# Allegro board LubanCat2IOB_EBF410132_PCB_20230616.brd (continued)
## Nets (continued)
GND: C3.2 C4.2 C5.2 C6.2 C7.2 C8.2 C9.2 C10.2 C12.2 C13.2 C15.2 C16.2 C17.2 C18.2 C19.2 C21.2 C22.2 C23.2 C25.2 C26.2 C27.2 C28.2 C30.2 C31.2 C33.2 C34.2 C35.2 C36.2 C37.2 C38.2 C39.2 C40.2 C41.2 C42.2 C43.2 C44.2 C45.2 C46.2 C47.2 C48.2 C51.2 C52.2 C55.2 C56.2 C57.2 C58.2 C59.2 C63.2 C64.2 C65.2 C66.2 C67.2 C70.2 C71.2 C72.2 C73.2 C74.2 C75.2 C76.2 C77.2 C78.2 C79.2 C80.2 C81.2 C82.2 C83.2 C84.2 C85.2 C86.2 C87.2 C88.2 C89.2 C90.2 C91.2 C92.2 C93.2 C94.2 C95.2 C96.2 C97.2 C98.2 C99.2 C100.2 C101.2 C102.2 C103.2 C104.2 C105.2 C106.2 C107.2 C108.2 C109.2 C110.2 C111.2 C112.2 C113.2 C114.2 C115.2 C116.2 C117.2 C118.2 C119.2 C120.2 C121.2 C122.2 C129.2 C130.2 C131.2 C132.2 C133.2 C134.2 C135.2 C136.2 C137.2 C138.2 C141.2 C144.2 C145.2 C146.2 C147.2 C148.2 C149.2 C150.2 C151.2 C152.2 C153.2 C154.2 C155.2 C156.2 C157.2 C158.2 C159.2 C160.2 C161.2 C162.2 C163.2 C164.2 C165.2 C166.2 C167.2 C168.2 C169.2 C170.2 C171.2 C172.2 C173.2 C174.2 C175.2 C176.2 C179.2 C180.2 C181.2 C182.2 C183.2 C184.2 C185.2 C186.2 C187.2 C188.2 C189.2 C190.2 C191.2 C192.2 C193.2 C194.2 C195.2 C196.2 C197.2 C198.2 C199.2 C200.2 C201.2 C202.2 C203.2 C204.2 C207.2 C208.2 C209.2 C210.2 C212.2 C213.2 C216.2 C218.2 D1.1 D2.1 D3.1 D6.2 D7.2 D8.2 D9.2 D10.2 D11.2 D12.2 D13.2 D15.1 D16.1 D17.1 D18.1 D19.2 D20.2(A) D23.2 D24.1 D25.2 D26.2 D28.1 D29.2 D30.2 D31.2 D32.2 D33.2 D34.2 D36.2 D37.2 J1.7 J1.8 J1.9 J1.10 J1.16 J1.20 J1.23 J1.26 J1.31 J1.32 J1.40 J1.49 J1.50 J1.56 J1.66 J1.67 J1.73 J1.76 J2.1 J2.2 J2.8 J2.11 J2.14 J2.27 J2.30 J2.40 J2.41 J2.55 J2.58 J2.64 J2.68 J2.69 J2.75 J2.79 J3.1 J3.2 J3.3 J3.13 J3.18 J3.23 J3.24 J3.26 J3.29 J3.36 J3.39 J3.49 J3.54 J3.55 J3.65 J3.66 J3.79 J3.80 J4.1 J4.2 J4.12 J4.23 J4.26 J4.33 J4.40 J4.54 J4.58 J4.64 J4.69 J4.70 J4.71 J4.73 J4.75 J4.76 J4.77 J4.78 J4.79 J4.80 J6.2 J7.3 J8.2 J8.5 J9.4 J11.10(CHS) J12.4 J15.6 J16.2 J17.1(CONFIG_3) J17.3(GND1) J17.9(GND2) J17.15(GND3) J17.21(CONFIG_0) J17.27(GND4) J17.33(GND5) J17.39(GND_6) J17.45(GND_7) J17.51(GND_8) J17.57(GND_9) J17.71(GND_10) J17.73(GND_11) J17.75(CONFIG_2) J17.76(G1) J17.77(G2) J18.10(CHS) J19.4(GND1) J19.7(GND2) J19.13(GND1) J19.16(NC3) J20.4(GND) J20.10(GND) J21.2 J21.5 J21.8 J21.11 J21.17 J22.4 J22.18 J22.21 J22.23 J22.24 J22.25(SH1) J22.26(SH2) J23.6 J23.7 J23.8 J23.16 J23.19 J23.22 J23.25 J23.28 J23.31(SH1) J23.32(SH2) J24.4 J24.23 J24.24 J24.25(SH1) J24.26(SH2) J26.6 J26.7 J26.8 J26.16 J26.19 J26.22 J26.25 J26.28 J26.31(SH1) J26.32(SH2) J28.6 J29.2 J29.5 J29.8 J29.11 J29.15 J29.16 J29.18 J29.19 J29.20 J29.21 J29.31(SH1) J29.32(SH2) J33.1 J34.1(GND1) J34.4(GND2) J34.7(GND3) J34.S1(SH1) J34.S2(SH2) J35.4(GND9) J35.9(GND1) J35.15(GND2) J35.18(GND10) J35.21(GND3) J35.26(GND11) J35.27(GND4) J35.29(GND5) J35.34(GND12) J35.35(GND6) J35.37(GND7) J35.40(GND13) J35.43(GND8) J35.50(GND14) J35.53 J35.54 J36.A1(GND1) J36.A12(GND2) J36.B1(GND4) J36.B12(GND3) J37.2 J37.4 J37.6 J39.2 J39.3 J40.2 J40.3 J41.6(VSS) J41.10(GND10) J41.11(GND11) J41.12(GND12) J41.13(GND13) L2.2 L19.2 L20.2 L21.2 LED1.2(CATHODE) Q4.2(EMITTER) Q14.2(SOURCE) R3.2 R7.2 R8.2 R12.2 R13.2 R15.2 R17.2 R27.2 R40.2 R41.2 R69.2 R70.2 R74.2 R75.2 R79.2 R82.2 R97.2 R98.2 R99.2 R100.2 R106.2 R108.2 R112.2 R121.2 R125.2 R126.2 R127.2 R131.2 R135.2 R137.2 R142.2 R143.2 R144.2 R155.2 R157.2 R159.2 R162.2 R163.2 R171.2 R173.2 R175.2 R176.2 R177.2 R183.2 R186.2 R188.1 R190.2 R192.2 R196.2 R197.2 R198.2 R199.2 R202.2 R203.2 R207.2 R212.2 R215.2 R216.2 R220.2 R234.2 R237.2 SS5.1(NC_1) SS6.1(NC_1) SS7.1(NC_1) SS8.1(NC_1) SS9.1(NC_1) SS10.1(NC_1) SS11.1(NC_1) SS12.1(NC_1) SS13.1(NC_1) SW1.1(A1) SW1.3(GND1) SW2.1(A1) SW2.3(GND1) SW3.1(A1) SW3.3(GND1) U1.1(GND) U2.1(GND) U3.1(GND1) U3.4(GND2) U4.1(\\O\E) U4.3(GND) U5.1(GND) U6.4(GND) U7.1(GND) U8.5(GND) U9.2(GND) U9.8(S) U10.2(GND) U10.8(S) U11.15(GND) U12.1(\\O\E) U12.3(GND) U13.5(GND) U14.5(GND) U14.8(SH1) U14.9(SH2) U14.10(SH3) U14.11(SH4) U15.2 U16.1(GND) U17.4(GND) U18.41(GND) U19.41(GND) U20.1(GND) U21.9(GNDXD) U21.16(GNDODA) U22.3(GND1) U22.8(GND2) U23.3(GND1) U23.8(GND2) U24.2(GND) U25.2(GND) U26.2(GND) U28.25(VSS) U29.2(GND) U30.3(GND1) U30.8(GND2) U31.3(GND1) U31.8(GND2) U32.3(GND1) U32.8(GND2) U33.2(GND) U34.2(GND) U35.2(GND) U36.2(GND) U37.2(GND) U38.2(GND) U39.2(GND) U40.2(GND) U41.1(GND) Y1.2(GND1) Y1.4(GND2) Y2.2(GND1) Y2.4(GND2) Y3.2(GND1) Y3.4(GND2) Y4.2(GND1) Y4.4(GND2)
VCC3V3_SD: C28.1 C30.1 J1.15 J1.17 J41.4(VDD)
VCC5V0_SYS: C24.2 C25.1 C26.1 J1.1 J1.2 J1.3 J1.4 J1.5 J1.6 L3.2 R4.1 R11.2
VCC5V0_USB: C140.2 C141.1 C159.1 L17.2 R235.2 U24.5(IN) U25.5(IN) U26.5(IN) U29.5(IN)
VCC5V0_USB20_HOST2: C144.1 C145.1 J19.10(VBUS) U24.1(OUT)
VCC5V0_USB20_HUB: C154.1 C155.1 C161.1 C162.1 C164.1 C165.1 J20.1(VBUS) J20.7(VBUS) U28.19(VDD5) U29.1(OUT)
VCC5V0_USB30_HOST: C148.1 C149.1 J19.1(VBUS) U26.1(OUT)
VCC_1V8: C22.1 C23.1 J1.11 J1.13 L10.2 L14.2 Q1.1(GATE) Q2.1(GATE) R24.1 R25.1 R45.1 R46.1 U6.8(VCC)
VCCA_1V8: J1.12 J1.14 R219.1
VCCIO_ACODEC: J1.19 J1.21 R210.1 R213.1
VDD_3V3: C12.1 C13.1 C14.2 C17.1 C21.1 C37.1 C40.1 D21.2 J37.5 L5.1 L6.1 L7.2 L11.2 L12.2 L15.2 L16.2 L35.2 Q6.1(GATE) Q8.1(GATE) R2.2 R6.2 R31.1 R32.1 R33.1 R35.1 R47.1 R48.1 R66.2 R72.1 R146.1 R147.1 R178.1 R180.1 R181.1 R236.2 U4.5(VCC) U9.5(VIO) U10.5(VIO) U12.5(VCC) U35.5(IN) U37.5(IN) U38.5(IN) U40.5(IN)
VDD_3V3_EDP_LCD: C183.1 C184.1 J29.12 J29.13 R187.1 U37.1(OUT)
VDD_3V3_EDP_TP: C202.1 C203.1 J28.1 R193.1 R194.1 U38.1(OUT)
VDD_5V: C2.2 C3.1 C4.1 C36.1 C38.1 C41.1 C43.1 C46.1 C79.1 C80.1 D14.1 J37.3 L1.2 Q3.2(SOURCE) Q7.1(GATE) R1.2 R9.1 U7.3(VIN) U9.3(VCC) U10.3(VCC) U20.3(VIN) U33.5(IN) U34.5(IN) U36.5(IN) U39.5(IN)
VDD_CAM0_5V: C169.1 C170.1 C171.1 J22.1 J22.2 J22.3 U33.1(OUT)
VDD_CAM1_5V: C173.1 C174.1 C175.1 J24.1 J24.2 J24.3 U36.1(OUT)
VDD_LCD0_3V3: C185.1 C190.1 C191.1 J23.4 J23.5 R167.1 R222.1 U35.1(OUT)
VDD_LCD0_5V: C186.1 C187.1 C188.1 J23.1 J23.2 J23.3 U34.1(OUT)
VDD_LCD1_3V3: C196.1 C198.1 C199.1 J26.4 J26.5 R223.1 R224.1 U40.1(OUT)
VDD_LCD1_5V: C194.1 C195.1 C197.1 J26.1 J26.2 J26.3 U39.1(OUT)
BAT_RTC: C67.1 D21.1 D24.2 J16.1
CAM0_NRST: J2.76 J22.22
CAM0_PWDN: J1.39 J22.15
CAM0_PWR_EN: J3.56 R174.1
CAM1_NRST: J2.80 J24.22
CAM1_PWDN: J2.78 J24.15
CAM1_PWR_EN: J3.58 R185.1
CAN1_H: J5.1 R39.1 U9.7(CANH)
CAN1_L: J5.2 R39.2 U9.6(CANL)
CAN1_RX_M1: J4.9 U9.4(RXD)
CAN1_TX_M1: J4.7 U9.1(TXD)
CAN2_H: J5.3 R42.1 U10.7(CANH)
CAN2_L: J5.4 R42.2 U10.6(CANL)
CAN2_RX: Q2.3(DRAIN) R48.2 U10.4(RXD)
CAN2_RX_M0: J4.8 Q2.2(SOURCE) R46.2
CAN2_TX: Q1.3(DRAIN) R47.2 U10.1(TXD)
CAN2_TX_M0: J4.10 Q1.2(SOURCE) R45.2
CC1: D27.2 J36.A5(CC1)
CC2: D27.1 J36.B5(CC2)
CTP0_INT: J3.8 J23.11 R167.2
CTP0_RST: J3.6 J23.12 R222.2
CTP1_INT: J4.49 J26.11 R223.2
CTP1_RST: J4.53 J26.12 R224.2
DGB_RX: D36.1 J7.2 R36.1
DGB_TX: D37.1 J7.1 R23.1
DSI0_RST: J3.16 J23.15
DSI0_TE: J3.4 R204.1
DSI1_RST: J4.57 J26.15
DSI1_TE: J4.55 R208.1
EDP_AUXN: C178.2 J29.10 R188.2
EDP_AUXP: C177.2 J29.9 R187.2
EDP_BL_EN: J4.45 J29.22
EDP_BL_PWM: J3.14 J29.23
EDP_HPDIN_M0: J2.66 J29.17
EDP_LCD_PWR_EN: J3.60 R189.2
EDP_TP_INT: J4.51 J28.2 R193.2
EDP_TP_PWR_EN: J3.64 R191.1
EDP_TP_RESET: J4.47 J28.3 R194.2
EDP_TX_AUXN: C178.1 J2.62
EDP_TX_AUXP: C177.1 J2.60
EDP_TX_D0N: J2.44 J29.6
EDP_TX_D0P: J2.42 J29.7
EDP_TX_D1N: J2.48 J29.3
EDP_TX_D1P: J2.46 J29.4
EXT_PWR_EN: J1.27 R8.1 U2.5(EN)
FAN_CTRL: J3.5 R10.1
FSPI_CLK: J2.29 U6.6(CLK)
FSPI_CS0N: J2.31 U6.1(C\S\)
FSPI_D0: J2.33 J32.1 U6.5(DI/IO0)
FSPI_D1: J2.35 U6.2(DO/IO1)
FSPI_D2: J2.37 R24.2 U6.3(W\P\/IO2)
FSPI_D3: J2.39 R25.2 U6.7(HOLD/IO3)
GMAC0_INT: J2.70 R104.1
GMAC0_MCLKINOUT: J2.77 R105.1 R106.1
GMAC0_MDC: J2.73 R101.2 U18.13(MDC)
GMAC0_MDIO: J2.71 R102.2 U18.14(MDIO)
GMAC0_RSTN: D22.2 J2.72
GMAC0_RXCLK: J2.57 R95.1 R98.1
GMAC0_RXD0: J2.67 R88.2 R91.1
GMAC0_RXD1: J2.65 R89.2 R92.1
GMAC0_RXD2: J2.63 R93.1 R97.1
GMAC0_RXD3: J2.61 R90.2 R94.1
GMAC0_RXDV_CRS: J2.59 R96.1 R99.1
GMAC0_TXCLK: J2.51 U18.20(TXC)
GMAC0_TXD0: J2.49 U18.18(TXD0)
GMAC0_TXD1: J2.47 U18.17(TXD1)
GMAC0_TXD2: J2.45 U18.16(TXD2)
GMAC0_TXD3: J2.43 U18.15(TXD3)
GMAC0_TXEN: J2.53 U18.19(TXCTL)
GMAC1_INT: J3.12 R132.1
GMAC1_MCLKINOUT_M1: J4.56 R134.1 R135.1
GMAC1_MDC_M1: J4.62 R128.2 U19.13(MDC)
GMAC1_MDIO_M1: J4.60 R129.2 U19.14(MDIO)
GMAC1_RSTN: D35.2 J3.10
GMAC1_RXCLK_M1: J4.36 R117.2 R123.1
GMAC1_RXD0_M1: J4.34 R115.2 R118.1
GMAC1_RXD1_M1: J4.32 R116.2 R119.1
GMAC1_RXD2_M1: J4.30 R120.1 R125.1
GMAC1_RXD3_M1: J4.28 R122.1 R126.1
GMAC1_RXDV_CRS_M1: J4.38 R124.1 R127.1
GMAC1_TXCLK_M1: J4.44 U19.20(TXC)
GMAC1_TXD0_M1: J4.52 U19.18(TXD0)
GMAC1_TXD1_M1: J4.50 U19.17(TXD1)
GMAC1_TXD2_M1: J4.48 U19.16(TXD2)
GMAC1_TXD3_M1: J4.46 U19.15(TXD3)
GMAC1_TXEN_M1: J4.42 U19.19(TXCTL)
HDMI_5V: C168.1 D14.2 D28.2 J21.18 R179.1 R182.1
HDMI_GND_CHASSIS: J21.G1(20) J21.G2(21) J21.G3(22) J21.G4(23) R177.1
HDMI_TX0N_PORT: J3.48 J21.9 U32.1(D1+) U32.10(NC1)
HDMI_TX0P_PORT: J3.46 J21.7 U32.2(D1-) U32.9(NC2)
HDMI_TX1N_PORT: J3.44 J21.6 U31.2(D1-) U31.9(NC2)
HDMI_TX1P_PORT: J3.42 J21.4 U31.1(D1+) U31.10(NC1)
HDMI_TX2N_PORT: J3.40 J21.3 U32.4(D2+) U32.7(NC3)
HDMI_TX2P_PORT: J3.38 J21.1 U32.5(D2-) U32.6(NC4)
HDMI_TX_CEC_PORT: D18.2 J21.13 Q7.3(DRAIN)
HDMI_TX_HPD_PORT: D15.2 J21.19 R172.2 R176.1
HDMI_TX_HPDIN: J3.34 R172.1
HDMI_TXCLKN_PORT: J3.50 J21.12 U31.5(D2-) U31.6(NC4)
HDMI_TXCLKP_PORT: J3.52 J21.10 U31.4(D2+) U31.7(NC3)
HDMI_TXDDC_SCL_PORT: D17.2 J21.15 Q6.3(DRAIN) R179.2
HDMI_TXDDC_SDA_PORT: D16.2 J21.16 Q8.3(DRAIN) R182.2
HDMITX_CEC_M0: J3.32 Q7.2(SOURCE) R180.2
HDMITX_SCL: J3.30 Q6.2(SOURCE) R178.2
HDMITX_SDA: J3.28 Q8.2(SOURCE) R181.2
HP_DET: C213.1 J1.35 R211.1
HP_SNS: J1.36 J25.5 J27.5 R212.1 R216.1
HPL_OUT: C214.1 J1.34
HPR_OUT: C215.1 J1.38
HUB_3V3: C156.1 C157.1 R164.2 R165.2 R166.2 R168.2 R169.1 U28.20(VDD33F)
I2C0_SCL: J2.3 U17.6(SCL)
I2C0_SDA: J2.5 U17.5(SDA)
I2C1_SCL: J2.7 J22.6 J23.9 R35.2
I2C1_SDA: J2.9 J22.5 J23.10 R33.2
I2C5_SCL_M0: J4.25 J24.6 J26.9 J28.4 R147.2
I2C5_SDA_M0: J4.27 J24.5 J26.10 J28.5 R146.2
LCD0_BL_PWM: J3.9 J23.13
LCD0_PWR_EN: J4.65 R195.1
LCD1_BL_PWM: J3.11 J26.13
LCD1_PWR_EN: J4.67 R200.2
LED_USR: J4.4 LED2.2(CATHODE)
M2PCIE_3V3: C69.2 C70.1 C71.1 C115.1 C116.1 C117.1 C118.1 C119.1 C120.1 C121.1 C122.1 C129.1 C130.1 C131.1 C136.1 J17.2(3.3V_1) J17.4(3.3V_2) J17.12(3.3V_3) J17.14(3.3V_4) J17.16(3.3V_5) J17.18(3.3V_6) J17.70(3.3V_7) J17.72(3.3V_8) J17.74(3.3V_9) L8.2 R73.2 R80.2 R81.2 R83.1 R84.1 R85.1 R86.1 R145.2 U21.1(VDDXD)
M2PCIE_PWR_EN: J1.41 R76.2
MDIN0_PHY0: J11.3(TD1-) U18.2(MDIN0)
MDIN0_PHY1: J18.3(TD1-) U19.2(MDIN0)
MDIN1_PHY0: J11.7(RD1-) U18.5(MDIN1)
MDIN1_PHY1: J18.7(RD1-) U19.5(MDIN1)
MDIN2_PHY0: J11.6(TD2-) U18.7(MDIN2)
MDIN2_PHY1: J18.6(TD2-) U19.7(MDIN2)
MDIN3_PHY0: J11.9(RD2-) U18.10(MDIN3)
MDIN3_PHY1: J18.9(RD2-) U19.10(MDIN3)
MDIP0_PHY0: J11.2(TD1+) U18.1(MDIP0)
MDIP0_PHY1: J18.2(TD1+) U19.1(MDIP0)
MDIP1_PHY0: J11.4(RD1+) U18.4(MDIP1)
MDIP1_PHY1: J18.4(RD1+) U19.4(MDIP1)
MDIP2_PHY0: J11.5(TD2+) U18.6(MDIP2)
MDIP2_PHY1: J18.5(TD2+) U19.6(MDIP2)
MDIP3_PHY0: J11.8(RD2+) U18.9(MDIP3)
MDIP3_PHY1: J18.8(RD2+) U19.9(MDIP3)
MIC1_INN: C217.2 D30.1 J1.30 J27.3 J27.4 J30.1 R215.1
MIC1_INP: C217.1 D29.1 J1.28 J27.1 J27.2 J30.2 R214.2
MINIPCIE_3V3: C32.1 C33.1 C34.1 C35.1 C55.1 C56.1 C57.1 C58.1 J35.2(VBAT1) J35.24(VBAT5) J35.39(VBAT2) J35.41(VBAT3) J35.52(VBAT4) L4.2 R14.1 R22.1
MINIPCIE_NWDISABLE: J4.61 R62.2
MINIPCIE_PWR_EN: J4.63 R16.1
MIPI_CSI_RX_CLK0N: J3.78 J22.10
MIPI_CSI_RX_CLK0P: J3.76 J22.9
MIPI_CSI_RX_CLK1N: J3.77 J24.10
MIPI_CSI_RX_CLK1P: J3.75 J24.9
MIPI_CSI_RX_D0N: J3.70 J22.12
MIPI_CSI_RX_D0P: J3.68 J22.11
MIPI_CSI_RX_D1N: J3.74 J22.8
MIPI_CSI_RX_D1P: J3.72 J22.7
MIPI_CSI_RX_D2N: J3.69 R227.1 R233.1
MIPI_CSI_RX_D2P: J3.67 R226.1 R232.1
MIPI_CSI_RX_D3N: J3.73 R229.1 R231.1
MIPI_CSI_RX_D3P: J3.71 R228.1 R230.1
MIPI_DSI_TX0_CLKN: J3.53 J23.24
MIPI_DSI_TX0_CLKP: J3.51 J23.23
MIPI_DSI_TX0_D0N: J3.43 J23.27
MIPI_DSI_TX0_D0P: J3.41 J23.26
MIPI_DSI_TX0_D1N: J3.47 J23.21
MIPI_DSI_TX0_D1P: J3.45 J23.20
MIPI_DSI_TX0_D2N: J3.59 J23.18
MIPI_DSI_TX0_D2P: J3.57 J23.17
MIPI_DSI_TX0_D3N: J3.63 J23.30
MIPI_DSI_TX0_D3P: J3.61 J23.29
MIPI_DSI_TX1_CLKN: J3.27 J26.24
MIPI_DSI_TX1_CLKP: J3.25 J26.23
MIPI_DSI_TX1_D0N: J3.17 J26.27
MIPI_DSI_TX1_D0P: J3.15 J26.26
MIPI_DSI_TX1_D1N: J3.21 J26.21
MIPI_DSI_TX1_D1P: J3.19 J26.20
MIPI_DSI_TX1_D2N: J3.33 J26.18
MIPI_DSI_TX1_D2P: J3.31 J26.17
MIPI_DSI_TX1_D3N: J3.37 J26.30
MIPI_DSI_TX1_D3P: J3.35 J26.29
OE: R83.2 U21.8(OE)
ON/OFF_KEY: C64.1 D2.2 J1.25 SW2.2(B1)
PCIE20_CLKREQN_M1: J4.37 R30.1
PCIE20_PERSTN_M1: J4.59 R63.2
PCIE20_REFCLKN: J1.54 J35.11(VDD-EXT)
PCIE20_REFCLKP: J1.52 J35.13(RESERVED)
PCIE20_RXN: J1.48 J35.23(UART-RXD)
PCIE20_RXP: J1.46 J35.25(UART-RTS)
PCIE20_TXN: C53.1 J1.44
PCIE20_TXP: C54.1 J1.42
PCIE20_WAKEN_M1: J4.39 R29.1
PCIE30_REFCLKN_IN: J1.71 R78.2 R79.1
PCIE30_REFCLKP_IN: J1.69 R77.2 R82.1
PCIE30_RX0N: J1.61 J17.41(SATA-/B+/PERN0)
PCIE30_RX0P: J1.59 J17.43(SATA-/B-/PERP0)
PCIE30_RX1N: J1.65 J17.29(PERN1)
PCIE30_RX1P: J1.63 J17.31(PERP1)
PCIE30_TX0N: C125.1 J1.53
PCIE30_TX0P: C126.1 J1.51
PCIE30_TX1N: C123.1 J1.57
PCIE30_TX1P: C124.1 J1.55
PCIE30X2_CLKREQN_M1: J1.75 J17.52(CLKREQ#)
PCIE30X2_PERSTN_M1: J1.79 J17.50(PERST#)
PCIE30X2_WAKEN_M1: J1.77 J17.54(PEWAKE#)
PDN: R84.2 U21.7(PDN)
PE_TXN: C53.2 J35.31(UART-TXD)
PE_TXP: C54.2 J35.33(PERST2)
PETN0: C125.2 J17.47(SATA-/A-/PETN0)
PETN1: C123.2 J17.35(PETN1)
PETP0: C126.2 J17.49(SATA-/A+/PETP0)
PETP1: C124.2 J17.37(PETP1)
PHY0_CLKOUT125: R105.2 U18.35(CLKOUT)
PHY0_LED1: J11.14(YELA) R108.1 U18.33(LED1)
PHY0_LED2: J11.12(GRLC) R109.1 U18.34(LED2)
PHY1_CLKOUT125: R134.2 U19.35(CLKOUT)
PHY1_LED1: J18.14(YELA) R137.1 U19.33(LED1)
PHY1_LED2: J18.12(GRLC) R138.1 U19.34(LED2)
PWM3_IR: J3.7 R34.1
RECOVERY_KEY: J2.16 R26.2
REF_CLKN: C127.1 R111.2 R112.1
REF_CLKP: C128.1 R87.2 R142.1
REFCLKN: C127.2 J17.53(REFCLKN)
REFCLKP: C128.2 J17.55(REFCLKP)
RESET_KEY: C63.1 D1.2 J1.29 SW1.2(B1)
RS232_3V3: C42.1 L7.1 U11.16(VCC)
RS232_R1IN: J8.4 U11.13(R1IN)
RS232_R1OUT: J13.1 U11.12(R1OUT)
RS232_R2IN: J8.1 U11.8(R2IN)
RS232_R2OUT: J14.1 U11.9(R2OUT)
RS232_T1IN: J13.2 U11.11(T1IN)
RS232_T1OUT: J8.6 U11.14(T1OUT)
RS232_T2IN: J14.2 U11.10(T2IN)
RS232_T2OUT: J8.3 U11.7(T2OUT)
RS485_1_3V3: C39.1 D4.1 L5.2 U8.8(VCC)
RS485_1_A: J10.2 R37.1 R38.2 U8.6(A)
RS485_1_B: J10.1 R38.1 R41.1 U8.7(B)
RS485_1_DIR: J4.41 R40.1 U8.2(R\E\) U8.3(DE)
RS485_2_3V3: C44.1 D5.1 L6.2 U13.8(VCC)
RS485_2_A: J10.4 R67.1 R68.2 U13.6(A)
RS485_2_B: J10.3 R68.1 R70.1 U13.7(B)
RS485_2_DIR: J4.43 R69.1 U13.2(R\E\) U13.3(DE)
RX8010_NIRQ1: J1.33 R72.2 U17.7(/IRQ1)
S0: R86.2 U21.2(S0)
S1: R85.2 U21.3(S1)
S2: R143.1 U21.4(S2)
SARADC_VIN1: J2.18 R55.1
SARADC_VIN3: J2.20 R219.2 R220.1
SARADC_VIN4: J2.22 R56.1
SARADC_VIN5: J2.24 R58.1
SARADC_VIN6: J2.26 R59.1
SARADC_VIN7: J2.28 R71.1
SATA0_RXN: C62.1 J1.70
SATA0_RXP: C211.1 J1.68
SATA0_TXN: C61.1 J1.74
SATA0_TXP: C60.1 J1.72
SATA0RXN: C62.2 J34.5(RXDN)
SATA0RXP: C211.2 J34.6(RXDP)
SATA0TXN: C61.2 J34.3(TXDN)
SATA0TXP: C60.2 J34.2(TXDP)
SATA_5V: C206.2 C207.1 C208.1 J40.1 L22.2 R201.2
SATA_12V: C59.1 C212.1 J40.4 Q10.3(DRAIN)
SATA_PWR_EN: J2.74 R206.1 R209.2
SDMMC0_CLK: J2.13 R54.1
SDMMC0_CMD: J2.15 R53.1
SDMMC0_D0: J2.19 R57.1
SDMMC0_D1: J2.21 R60.1
SDMMC0_D2: J2.23 R51.1
SDMMC0_D3: J2.25 R52.1
SDMMC0_DET: J2.17 R61.1
SIM_CLK0: J35.12(USIM-CLK) R20.1
SIM_DATA0: J35.10(USIM-DATA) R21.1
SIM_RST0: J35.14(USIM-RST) R19.1
SIM_VDD: J35.8(USIM-VDD) R18.1 U14.1(VCC) U15.6
SPKN_OUT: J1.24 R218.1
SPKP_OUT: J1.22 R217.1
U7_RX: J9.3 J13.5
U7_TX: J9.2 J13.6
U9_RX: J12.3 J14.5
U9_TX: J12.2 J14.6
UART2_RX: R36.2 U12.2(A)
UART2_RX_M0_DEBUG: J3.22 U12.4(Y)
UART2_TX: R23.2 U4.4(Y)
UART2_TX_M0_DEBUG: J3.20 U4.2(A)
UART3_RX_M1: J4.13 U8.1(RXD)
UART3_TX_M1: J4.11 U8.4(TXD)
UART4_RX_M1: J4.17 U13.1(RXD)
UART4_TX_M1: J4.15 U13.4(TXD)
UART7_RX: D9.1 J13.3 R50.2
UART7_RX_M1: J4.21 R50.1
UART7_TX: D8.1 J13.4 R49.2
UART7_TX_M1: J4.19 R49.1
UART9_RX: D7.1 J14.3 R44.2
UART9_RX_M1: J4.5 R44.1
UART9_TX: D6.1 J14.4 R43.2
UART9_TX_M1: J4.3 R43.1
USB2_HOST2_DM: J4.74 R152.2
USB2_HOST2_DP: J4.72 R153.2
USB2_HOST3_DM: J4.68 U28.14(DMU)
USB2_HOST3_DP: J4.66 U28.15(DPU)
USB3_HOST1_DM: J1.80 R148.2
USB3_HOST1_DP: J1.78 R149.2
USB3_HOST1_SSRXN: J1.60 R150.2
USB3_HOST1_SSRXP: J1.58 R151.2
USB3_HOST1_SSTXN: C142.2 J1.64
USB3_HOST1_SSTXP: C143.2 J1.62
USB3_OTG0_DM: D26.1 J2.6 J36.A7(DN1) J36.B7(DN2)
USB3_OTG0_DP: D25.1 J2.4 J36.A6(DP1) J36.B6(DP2)
USB3_OTG0_ID: J2.10 R160.2
USB3_OTG0_VBUSDET: J2.12 R158.2 R159.1
USB20_DM1: J19.11(D-) R152.1 U22.4(D2+) U22.7(NC3)
USB20_DP1: J19.12(D+) R153.1 U22.5(D2-) U22.6(NC4)
USB20_HOST2_PWR_EN: J1.45 R154.1
USB20_HUB_PWR_EN: J3.62 R170.1
USB30_DM: J19.2(D-) R148.1 U23.5(D2-) U23.6(NC4)
USB30_DP: J19.3(D+) R149.1 U23.4(D2+) U23.7(NC3)
USB30_HOST1_PWR_EN: J1.47 R156.1
USB30_RXN: J19.5(RX-) R150.1 U23.2(D1-) U23.9(NC2)
USB30_RXP: J19.6(RX+) R151.1 U23.1(D1+) U23.10(NC1)
USB30_TXN: C142.1 J19.8(TX-) U22.2(D1-) U22.9(NC2)
USB30_TXP: C143.1 J19.9(TX+) U22.1(D1+) U22.10(NC1)
USB_HUB_DM1: J20.2(D-) U28.11(DM1) U30.2(D1-) U30.9(NC2)
USB_HUB_DM2: J20.8(D-) U28.9(DM2) U30.5(D2-) U30.6(NC4)
USB_HUB_DM3: R64.2 U28.7(DM3)
USB_HUB_DP1: J20.3(D+) U28.12(DP1) U30.1(D1+) U30.10(NC1)
USB_HUB_DP2: J20.9(D+) U28.10(DP2) U30.4(D2+) U30.7(NC3)
USB_HUB_DP3: R65.2 U28.8(DP3)
USB_OTG_VBUS: C151.1 C152.1 D23.1 J36.A4(VBUS1) J36.A9(VBUS2) J36.B4(VBUS4) J36.B9(VBUS3) R158.1 U25.1(OUT)
USB_OTG_VBUS_EN: J1.43 R161.1
N28501: C20.1 U5.6(BOOT)
N28533: C20.2 L3.1 U5.2(SW)
N28611: C24.1 R11.1 R13.1 U5.4(FB)
N15580021: R91.2 U18.25(RXD0)
N15580025: R92.2 U18.24(RXD1)
N15580029: R93.2 U18.23(RXD2)
N15580033: R94.2 U18.22(RXD3)
N15580037: R95.2 U18.27(RXC)
N15580041: R96.2 U18.26(RXCTL)
N15582684: R103.2 R104.2 U18.31(INTB)
N15584123: C77.1 U18.36(XTAL_IN) Y3.3
N15584130: C76.1 U18.37(XTAL_OUT) Y3.1
N15584385: C78.1 D22.1 R107.2 R184.2 U18.12(PHYRSTB)
N15584944: R110.1 U18.32(LED0)
N15590150: L9.1 U18.30(REG_OUT)
N15590489: R100.1 U18.39(RSET)
N15599533: R118.2 U19.25(RXD0)
N15599537: R119.2 U19.24(RXD1)
N15599541: R120.2 U19.23(RXD2)
N15599545: R122.2 U19.22(RXD3)
N15599549: R123.2 U19.27(RXC)
N15599553: R124.2 U19.26(RXCTL)
N15600826: R130.2 R132.2 U19.31(INTB)
N15601838: C98.1 U19.37(XTAL_OUT) Y4.1
N15601846: C99.1 U19.36(XTAL_IN) Y4.3
N15602147: C101.1 D35.1 R136.2 R238.2 U19.12(PHYRSTB)
N15602572: R139.1 U19.32(LED0)
N15603170: C100.1 J18.1(CT)
N15605093: L13.1 U19.30(REG_OUT)
N15605512: R121.1 U19.39(RSET)
N15772454: J26.14 R208.2
N15774097: J23.14 R204.2
N16795890: R12.1 R225.1 U5.5(EN)
N17344359: J39.1 J39.5 L2.1
N17345181: C11.2 L35.1 U2.2(SW)
N17345183: C14.1 R6.1 R7.1 U2.4(FB)
N17345235: C11.1 U2.6(BOOT)
N17366990: C1.1 U1.6(BOOT)
N17366996: C1.2 L1.1 U1.2(SW)
N17367006: C2.1 R1.1 R3.1 U1.4(FB)
N17371141: LED1.1(ANODE) R4.2
N17385739: LED2.1(ANODE) R31.2
N17407470: J41.1(DAT2) R51.2
N17407472: J41.7(DAT0) R57.2
N17407474: J41.5(CLK) R54.2
N17407476: J41.3(CMD) R53.2
N17407478: J41.2(CD/DAT3) R52.2
N17407480: J41.8(DAT1) R60.2
N17407510: J41.9(CD) R61.2
N17408573: C31.1 J11.1(CT)
N17409816: C29.1 L4.1 U7.2(SW)
N17409833: R16.2 R17.1 U7.5(EN)
N17409879: C32.2 R14.2 R15.1 U7.4(FB)
N17410026: C29.2 U7.6(BOOT)
N17410340: C52.1 R19.2 U14.2(RST) U15.5
N17410342: C51.1 R20.2 U14.3(CLK) U15.4
N17410344: C47.1 R18.2 R21.2 U14.7(I/O) U15.1
N17411312: J35.1(MIC-P) R22.2 R29.2
N17411326: J35.7(SPK-N) R30.2
N17411361: J35.20(W-DISABLE) R62.1
N17411393: J35.22(PERST1) R63.1
N17411481: J35.38(USB-D+) R65.1
N17411507: J35.36(USB-D-) R64.1
N17438974: D4.2 R37.2
N17440531: D5.2 R67.2
N17441588: C49.1 U11.3(C1-)
N17441590: C49.2 U11.1(C1+)
N17441592: C50.1 U11.5(C2-)
N17441594: C50.2 U11.4(C2+)
N17441596: C48.1 U11.6(V-)
N17441598: C45.1 U11.2(V+)
N17468430: C66.1 D21.3 U17.8(VDD)
N17485809: R75.1 R76.1 U20.5(EN)
N17485853: C68.1 U20.6(BOOT)
N17485857: C68.2 L8.1 U20.2(SW)
N17485876: C69.1 R73.1 R74.1 U20.4(FB)
N17487342: J17.38(DEVSLP) R81.1
N17487441: J17.10(DAS/DSS) R80.1
N17494240: J19.19(SH1) J19.20(SH2) J19.21(SH1) J19.22(SH2) L19.1
N17495021: C147.1 R156.2 U26.4(EN)
N17495041: R157.1 U26.3(ISET)
N17495139: C146.1 R154.2 U24.4(EN)
N17495165: R155.1 U24.3(ISET)
N17495663: J36.C1(SH1) J36.C2(SH2) J36.C3(SH3) J36.C4(SH4) L20.1
N17495859: D27.3 R160.1
N17496265: R162.1 U25.3(ISET)
N17496334: C150.1 R161.2 U25.4(EN)
N17505436: R163.1 U28.13(REXT)
N17505526: R164.1 U28.16(XRSTJ)
N17505593: R165.1 U28.18(BUSJ)
N17505596: C153.1 R166.1 U28.17(VBUSM)
N17506485: R168.1 U28.21(DRV)
N17506866: C158.1 R169.2 U28.1(OVCJ)
N17515649: C138.1 U28.3(XOUT) Y2.1
N17515683: C137.1 U28.4(XIN) Y2.3
N17516865: J20.5(SH1) J20.6(SH2) J20.11(SH1) J20.12(SH2) L21.1
N17517489: C163.1 R170.2 U29.4(EN)
N17517506: R171.1 U29.3(ISET)
N17532429: D19.1 J15.1 R55.2
N17532431: D13.1 J15.2 R56.2
N17532433: D12.1 J15.3 R58.2
N17532435: D11.1 J15.4 R59.2
N17532437: D10.1 J15.5 R71.2
N17536330: C15.1 C16.1 R66.1 U3.2(VCC)
N17536407: R32.2 R34.2 U3.3(OUT)
N17536851: C65.1 D3.2 R26.1 SW3.2(B1)
N17545096: C172.1 R174.2 U33.4(EN)
N17545112: R175.1 U33.3(ISET)
N17546367: J24.8 R231.2
N17546373: J24.12 R233.2
N17546399: J24.7 R230.2
N17546411: J24.11 R232.2
N17548144: C176.1 R185.2 U36.4(EN)
N17548162: R186.1 U36.3(ISET)
N17550903: R190.1 U37.3(ISET)
N17550993: C201.1 R189.1 U37.4(EN)
N17558620: R192.1 U38.3(ISET)
N17558699: C204.1 R191.2 U38.4(EN)
N17562506: C189.1 C192.1 R195.2 U34.4(EN) U35.4(EN)
N17562520: R196.1 U34.3(ISET)
N17562633: R197.1 U35.3(ISET)
N17563970: C193.1 C200.1 R200.1 U39.4(EN) U40.4(EN)
N17564290: R198.1 U39.3(ISET)
N17565184: R199.1 U40.3(ISET)
N17577061: R202.1 R209.1 U41.5(EN)
N17577092: C205.1 U41.6(BOOT)
N17577104: C205.2 L22.1 U41.2(SW)
N17577114: C206.1 R201.1 R203.1 U41.4(FB)
N17577685: Q10.1(GATE) Q14.3(DRAIN) R205.2
N17577722: Q14.1(GATE) R206.2 R207.1
N17590789: C215.2 D34.1 J25.3 J25.4
N17590802: C214.2 D33.1 J25.2 R211.2
N17590849: J25.1 R210.2
N17609931: C216.1 R213.2 R214.1
N17615054: D31.1 J31.1 R217.2
N17615057: D32.1 J31.2 R218.2
N17639389: C132.1 U21.5(X1) Y1.1
N17639396: R144.1 U21.10(IREF)
N17639427: C134.1 C135.1 R145.1 U21.15(VDDODA)
N17639486: R77.1 U21.20(CLK0P)
N17639523: R78.1 U21.19(CLK0N)
N17639615: R87.1 U21.18(CLK1P)
N17639617: R111.1 U21.17(CLK1N)
N17639713: C133.1 R221.1 Y1.3
N17683065: R2.1 U1.5(EN)
N17697748: R221.2 U21.6(X2)
N17699685: J11.11(GRLA) R28.1
N17699996: J11.13(YELC) R27.1
N17700387: J18.11(GRLA) R133.1
N17700720: J18.13(YELC) R131.1
N17737040: J22.16 R226.2
N17737043: J22.17 R227.2
N17737126: J22.19 R228.2
N17737138: J22.20 R229.2
N17802924: Q3.1(GATE) Q4.3(COLLECTOR) R9.2
N17802940: Q4.1(BASE) R10.2 R234.1
N17802978: D20.1(K) J6.1 R5.2
N17803061: Q3.3(DRAIN) R5.1
N17804550: R236.1 U16.5(EN)
N17804594: C139.1 U16.6(BOOT)
N17804606: C139.2 L17.1 U16.2(SW)
N17804616: C140.1 R235.1 R237.1 U16.4(FB)
N17822498: C166.1 J11.15(SH) J11.16(SH1) R173.1
N17836581: C167.1 J18.15(SH) J18.16(SH1) R183.1

Pads without a net: J1 18 37; J2 32 34 36 38 50 52 54 56; J4 6 14 16 18 20 22 24 29 31 35; J9 1; J12 1; J17 5 6 7 8 11 13 17 19 20 22 23 24 25 26 28 30 32 34 36 40 42 44 46 48 56 58 67 68 69; J19 14 15 17 18; J21 14; J22 13 14; J24 13 14 16 17 18 19 20 21; J29 1 14 24 25 30; J35 3 5 6 16 17 19 28 30 32 42 44 45 46 47 48 49 51; J36 A8 B8; NOREF 1; NOREF#2 1; NOREF#3 1; NOREF#5 1; NOREF#6 1; NOREF#7 1; NOREF#8 1; NOREF#10 1; NOREF#11 1; NOREF#12 1; NOREF#13 1; NOREF#14 1; NOREF#15 1; NOREF#16 1; NOREF#17 1; NOREF#18 1; U14 4 6; U15 3; U17 1 2 3; U21 11 12 13 14; U28 2 5 6 22 23 24

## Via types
v1: diameter 0.508, hole 0.305, TOP to BOTTOM, 1890 vias

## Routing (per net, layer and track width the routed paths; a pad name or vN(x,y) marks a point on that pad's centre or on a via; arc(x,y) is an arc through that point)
1V05_AVDD_PHY0: length 26.8
  TOP w0.173: U18.38 74.31,77.5 v1(74.44,77.63)
  TOP w0.203: U18.8 69.89,79.84 v1(69.9,79.85) ; v1(71.89,79.85) U18.3
  TOP w0.305: R114.2 v1(75.46,66.47)
  ART04 w0.305: v1(74.44,77.63) 74.44,74.32 76.35,72.41 76.35,67.36 v1(75.46,66.47)
  BOTTOM w0.305: R114.2 v1(75.46,66.47) ; C84.1 74.07,77.26 v1(74.44,77.63) 74.46,77.63 75.01,78.18 75.01,79.14 74.7,79.45 72.3,79.45 v1(71.89,79.85) v1(69.9,79.85) 69.9,79.83 70,79.73 C86.1 C87.1
1V05_AVDD_PHY1: length 27.2
  TOP w0.173: v1(93.62,77.63) 93.48,77.5 U19.38
  TOP w0.203: U19.3 v1(91.07,79.9) ; U19.8 v1(89.07,79.88)
  TOP w0.305: R141.2 v1(94.64,66.47)
  ART04 w0.305: v1(94.64,66.47) 95.83,67.66 95.83,77.19 95.39,77.63 v1(93.62,77.63) 91.4,77.63 91.08,77.95 91.08,79.89 v1(91.07,79.9)
  BOTTOM w0.305: v1(89.07,79.88) 89.03,79.84 89.03,79.18 C107.1 C108.1 v1(91.07,79.9) ; v1(93.62,77.63) 93.62,77.28 93.34,77.01 C106.1 ; R141.2 v1(94.64,66.47)
1V05_DVDD_PHY0: length 19.4
  TOP w0.173: 69.09,73.35 U18.21
  TOP w0.305: 69.09,73.35 68.86,73.12 68.11,73.12 v1(67.59,73.64) ; R113.1 v1(74.19,66.47)
  ART04 w0.305: v1(74.19,66.47) 74.19,67.05 74.55,67.41 74.55,72.23 72.87,73.91 67.86,73.91 v1(67.59,73.64)
  BOTTOM w0.305: v1(67.59,73.64) 67.79,73.84 C83.1 ; R113.1 v1(74.19,66.47)
1V05_DVDD_PHY1: length 22.2
  TOP w0.173: 88.27,73.35 U19.21
  TOP w0.305: R140.1 v1(93.37,66.47) ; v1(86.77,73.64) 87.29,73.12 88.04,73.12 88.27,73.35
  ART04 w0.305: v1(86.77,73.64) 87.24,74.11 94.44,74.11 95.05,73.5 95.05,68.14 v1(93.37,66.47)
  BOTTOM w0.305: v1(86.77,73.64) 86.96,73.84 C103.1 ; R140.1 v1(93.37,66.47)
1V05_PHY0: length 2.4
  TOP w0.305: C75.1 77.17,68.24 77.47,68.54 v1(77.47,69.01)
  BOTTOM w0.305: v1(77.47,69.01) 77.47,68.97 C75.1
1V05_PHY1: length 1.3
  TOP w0.305: C97.1 v1(96.54,68.24)
  BOTTOM w0.305: C97.1 v1(96.54,68.24)
1V8_DVDD_PHY0: length 38.3
  TOP w0.203: U18.28 71.89,72.75 v1(72.53,72.11)
  TOP w0.305: R107.1 v1(62.61,75.08) ; R90.1 67.34,66.8 68.22,65.91 69.06,65.91 v1(69.62,66.47) R89.1 R88.1
  ART04 w0.305: v1(69.62,66.47) 70.74,66.47 71.5,67.23 73.33,67.23 73.89,67.79 73.89,71.5 73.28,72.11 v1(72.53,72.11) 72.5,72.11 71.93,71.55 63.22,71.55 62.61,72.16 v1(62.61,75.08)
  BOTTOM w0.305: C73.1 C81.1 71.27,72.51 71.65,72.13 72.51,72.13 v1(72.53,72.11) ; v1(62.61,75.08) 63.1,75.08 63.41,75.38 R101.1 R102.1
1V8_DVDD_PHY1: length 42
  TOP w0.203: U19.28 91.07,72.75 v1(91.67,72.15)
  TOP w0.305: 88.8,66.47 88.06,65.73 86.88,65.73 C102.1 ; 88.8,66.47 R116.1 R115.1 ; 88.8,66.47 89.38,65.88 91.64,65.88 v1(92.23,66.47) R117.1 ; R136.1 82.12,75.13 81.79,75.46 v1(81.79,76.36)
  ART04 w0.305: v1(81.79,76.36) 81.79,72.28 82.4,71.67 91.2,71.67 v1(91.67,72.15) 92.94,72.15 93.55,71.54 93.55,67.79 v1(92.23,66.47)
  BOTTOM w0.305: R129.1 R128.1 81.8,76.35 v1(81.79,76.36) ; v1(91.67,72.15) 90.45,73.37 C94.1 C95.1
3V3_AVDD_PHY0: length 16.9
  TOP w0.203: v1(74.44,78.63) 74.22,78.63 73.89,78.3 U18.40 ; v1(67.46,78.55) 67.71,78.3 U18.11
  TOP w0.305: L12.1 64.41,79.07 C92.1 C91.1 64.8,77.09 65.08,77.36 65.08,78.33 65.3,78.55 v1(67.46,78.55)
  ART03 w0.305: v1(67.46,78.55) 74.36,78.55 v1(74.44,78.63)
  BOTTOM w0.305: v1(74.44,78.63) 74.09,78.28 C93.1
3V3_AVDD_PHY1: length 16.8
  TOP w0.203: v1(93.62,78.63) 93.4,78.63 93.06,78.3 U19.40 ; U19.11 86.97,78.3 v1(86.82,78.46)
  TOP w0.305: L16.1 83.53,79.17 C113.1 C114.1 84.01,77.16 84.33,77.47 84.33,78.25 84.53,78.46 v1(86.82,78.46)
  ART03 w0.305: v1(93.62,78.63) 87,78.63 v1(86.82,78.46)
  BOTTOM w0.305: v1(93.62,78.63) 93.62,78.43 93.22,78.02 C112.1
3V3_DVDD_PHY0: length 51.1
  TOP w0.203: v1(72.53,73.11) 72.29,73.35 U18.29
  TOP w0.305: R109.2 v1(77.6,75.1) 78.41,75.1 78.64,74.88 78.64,73.35 78.36,73.07 v1(77.6,73.07) R110.2 ; 66.22,71.67 66.22,70.93 ; 66.22,71.67 66.42,71.88 67.18,71.88 67.59,72.28 v1(67.59,72.64) ; 66.22,71.67 66.01,71.88 62.92,71.88 62.28,72.51 62.28,73.68 62.66,74.06 R184.1
  ART04 w0.305: v1(72.53,73.11) 68.06,73.11 v1(67.59,72.64)
  ART04 w0.381: v1(70.08,91.26) 70.08,86.86 70.51,86.43 76.2,86.43 76.96,85.67 76.96,75.74 v1(77.6,75.1)
  BOTTOM w0.305: v1(77.6,73.07) R103.1 75.71,73.84 C89.1 C90.1 72.29,73.35 v1(72.53,73.11)
  BOTTOM w0.381: R28.2 70.83,92.01 v1(70.08,91.26)
3V3_DVDD_PHY1: length 59.3
  TOP w0.203: U19.29 91.47,73.35 v1(91.67,73.15)
  TOP w0.305: 85.37,71.62 85.77,72.02 v1(85.77,72.64) ; 85.37,71.62 C109.1 ; 85.37,71.62 84.94,72.06 81.58,72.06 81.15,72.49 81.15,73.76 81.51,74.11 R238.1 ; R139.2 v1(96.77,73.07) 97.61,73.07 97.92,73.38 97.92,74.65 97.46,75.1 R138.2
  TOP w0.381: v1(97.21,93.57) 97.69,93.09 97.69,85.09 100.71,82.06 100.71,75.61 100.2,75.1 98.37,75.1 97.92,74.65
  ART04 w0.305: v1(91.67,73.15) 91.16,72.64 v1(85.77,72.64)
  BOTTOM w0.305: v1(96.77,73.07) R130.1 94.89,73.84 C110.1 C111.1 91.47,73.35 v1(91.67,73.15)
  BOTTOM w0.381: R133.2 90.23,92.01 91.77,93.54 97.18,93.54 v1(97.21,93.57)
12V: length 20.5
  TOP w0.305: v1(6.09,54.4) 6.03,54.46 U1.3 ; U2.3 6.02,40.49 v1(6.08,40.43) ; v1(136.76,11.3) 136.59,11.48 R205.1 ; J29.29 149.8,30.55 ; J29.27 149.8,29.55 ; C180.1 146.05,29.21 v1(145.72,29.54) ; J29.26 149.8,29.05 ; v1(136.76,12.3) 136.28,12.79 Q10.2 ; v1(6.1,68.36) 6.03,68.43 U5.3 ; J29.28 149.8,30.05
  ART04 w0.508: J37.1 20.73,15.7 ; J37.1 20,16.43 ; J37.1 20,14.97 ; J37.1 19.27,15.7
  BOTTOM w0.305: R225.2 C27.1 5.96,68.5 v1(6.1,68.36) ; C10.1 5.97,54.53 v1(6.09,54.4)
  vias: v1(1.61,79.8) v1(1.61,78.8) v1(1.61,77.8) v1(2.61,79.8) v1(3.61,79.8) v1(6.1,70.36) v1(6.1,69.36) v1(6.09,56.4) v1(6.09,55.4) v1(6.08,42.43) v1(6.08,41.43) v1(7.1,70.36) v1(7.1,69.36) v1(7.1,68.36) v1(7.09,56.4) v1(7.09,55.4) v1(7.09,54.4) v1(7.08,42.43) v1(7.08,41.43) v1(7.08,40.43) v1(9.76,82.04) v1(9.76,81.04) v1(9.76,80.04) v1(10.76,80.04) v1(11.76,82.04) v1(11.76,81.04) v1(11.76,80.04) v1(12.76,82.04) v1(12.76,81.04) v1(12.76,80.04) v1(113.52,27.89) v1(113.52,26.89) v1(114.52,27.89) v1(114.52,26.89) v1(115.52,27.89) v1(115.52,26.91) v1(137.76,12.3) v1(137.76,11.3) v1(146.72,29.54) v1(147.72,29.54) v1(148.72,29.54)
GND: length 3327.2
  TOP w0.203: SS8.1 129,51.57
  TOP w0.254: J4.75 v1(75.78,61.94) ; v1(62.28,65.94) 62.84,65.38 62.84,63.5 J4.23 ; J3.26 v1(38.28,60.94) ; J4.78 v1(76.28,57.94) ; J4.79 v1(76.78,61.94) ; J2.58 v1(71.28,27.89) ; J3.3 v1(32.78,64.94) ; J4.69 v1(74.28,64.94) ; J4.2 v1(57.28,57.94) ; v1(36.78,55.94) 37.78,56.94 J3.24 ; J4.77 v1(76.28,64.94) ; J4.1 v1(57.28,64.94) ; J4.80 v1(76.78,60.94) ; J1.8 33.78,27.64 v1(34.04,27.89) 34.28,27.64 J1.10 ; J3.23 v1(37.78,61.94) ; v1(59.56,60.91) 59.78,60.68 J4.12 ; v1(36.04,27.89) 35.78,27.64 J1.16 ; J3.2 v1(32.28,60.94) ; J4.73 v1(75.28,64.94) ; J1.7 33.78,23.64 v1(34.04,23.89) 34.28,23.64 J1.9 ; J2.14 v1(60.28,27.89) ; J2.40 v1(66.78,27.89) ; J2.75 v1(75.78,23.89) ; J4.71 v1(74.78,61.94) ; J2.64 v1(72.78,27.89) ; J1.31 v1(39.78,23.89) ; J3.29 v1(39.28,61.94) ; J2.1 v1(57.28,23.89) ; J4.33 v1(65.28,61.94) ; J3.13 v1(35.28,61.94) ; J3.18 v1(36.28,60.94) ; J2.30 v1(64.28,27.89) ; J2.79 v1(76.78,23.89) ; J2.68 v1(73.78,27.89)
  TOP w0.305: C23.2 C22.2 v1(61.97,19.83) ; v1(140.15,90.75) J17.15 v1(140.15,93.3) ; v1(90.1,63.86) 90.9,63.06 90.9,62.45 90.34,61.9 90.34,57.06 88.21,54.94 74.17,54.94 72.78,56.32 ; v1(72.78,27.89) 72.78,30.94 73.83,31.98 130.17,31.98 131.09,31.06 138.33,31.06 139.65,32.38 141.17,32.38 141.25,32.46 v1(141.25,32.46) ; R127.2 v1(91.08,66.47) ; v1(149.28,67.01) 149.23,66.97 C190.2 C185.2 ; J26.28 v1(146.3,55.19) 133.85,55.19 130.97,58.07 v1(121.69,58.07) ; C72.2 v1(66.19,69.06) C88.2 ; R202.2 v1(119.63,18.92) ; v1(146.69,69.72) 146.64,69.77 U36.2 ; R3.2 0.84,57.44 v1(0.83,57.45) ; 102.26,73.86 102.25,73.87 ; v1(146.71,39.92) U39.2 v1(144.73,39.92) ; v1(115.98,80.36) U29.2 113.69,80.36 v1(113.67,80.39) 113.52,80.24 C161.2 C162.2 111.79,79.23 R171.2 ; 66.78,32.72 66.74,32.68 R220.2 ; 66.78,32.72 v1(66.78,27.89) ; 66.78,32.72 69.22,35.15 138.4,35.15 139.06,34.49 v1(141.27,34.49) ; v1(137.15,90.75) J17.3 v1(137.15,93.3) ; v1(146.71,61.74) 146.69,61.77 U34.2 ; v1(123.64,37.05) 122.87,36.29 118.44,36.29 v1(117.69,37.04) ; v1(138.43,56.66) v1(137.43,56.66) v1(136.43,56.66) 134.04,56.66 131.29,59.41 v1(121.69,59.41) 119.35,59.41 arc(118.85,59.61) 118.64,60.11 118.64,60.73 arc(118.56,61.13) 118.33,61.47 v1(117.98,61.83) v1(116.97,61.83) v1(115.97,61.83) v1(115.97,60.83) ; v1(138.43,56.66) v1(139.43,56.66) v1(143.08,56.66) ; v1(138.43,56.66) R74.2 ; 74.28,57.08 74.96,56.41 87.2,56.41 88.14,57.35 88.14,62.87 v1(89.13,63.86) ; v1(141.65,90.75) J17.21 v1(141.65,93.3) ; C133.2 139.81,73.97 v1(140.22,73.97) U21.9 ; v1(121.69,56.79) 130.51,56.79 133.6,53.69 v1(146.3,53.69) J26.25 ; U3.1 149.41,95.88 v1(149.35,95.83) ; R7.2 1.09,43.47 v1(0.83,43.21) ; C171.2 C170.2 147.46,58.47 U33.2 ; J35.21 v1(117.5,75.31) ; R137.2 v1(96.77,74.09) ; J29.16 152.16,24.05 arc(152.3,24.02) 152.41,23.94 v1(152.55,23.8) 152.4,23.65 arc(152.29,23.57) 152.15,23.55 J29.15 ; C189.2 v1(140.6,63.55) ; 45.78,40.27 49.96,44.45 92.35,44.45 v1(92.46,44.34) 92.57,44.45 109.37,44.45 v1(109.5,44.57) ; C17.2 v1(8.76,26.34) ; v1(118.44,29.33) 118.37,29.26 C209.2 117.95,27.39 C210.2 118.43,25.61 U41.1 ; R203.2 v1(116.59,18.92) ; v1(125.48,74.57) 125.5,74.6 J35.9 ; U4.3 v1(5.96,27.23) ; v1(138.65,90.75) J17.9 v1(138.65,93.3) ; C193.2 140.6,41.35 arc(140.56,41.55) 140.44,41.72 v1(140.21,41.96) ; C97.2 v1(95.91,66.47) ; J35.35 v1(111.9,75.31) ; U4.1 v1(7.26,27.23) ; U12.1 v1(3.07,27.23) ; v1(48.54,39.01) 51.54,42.01 119.38,42.01 120.67,43.3 ; v1(137.08,8.27) 136.65,7.83 Q14.2 ; v1(98.85,99.17) v1(95.04,99.17) v1(91.23,99.17) v1(90.23,99.17) v1(89.23,99.17) v1(87.42,99.17) v1(86.42,99.17) v1(83.61,99.17) v1(82.61,99.17) v1(81.61,99.17) v1(79.8,99.17) v1(75.99,99.17) v1(72.18,99.17) v1(71.18,99.17) v1(68.71,99.17) v1(67.71,99.17) v1(66.71,99.17) v1(65.71,99.17) v1(63.97,99.17) 63.92,99.22 v1(62.09,99.22) 62.05,99.17 v1(60.75,99.17) ; D30.2 46.82,81.28 v1(46.81,81.28) ; D11.2 v1(110.34,22.06) ; J21.2 56.2,93.81 55.04,94.97 52.6,94.97 ; v1(40.88,81.28) 40.89,81.28 D29.2 ; R126.2 R125.2 v1(87.66,66.47) ; C188.2 C186.2 149.2,62.9 v1(149.28,62.83) ; v1(150.28,63.83) 150.28,64.33 149.67,64.94 C191.2 ; C99.2 v1(96.77,77.14) ; v1(144.71,43.91) 144.79,43.99 U40.2 146.63,43.99 v1(146.71,43.91) ; v1(134.39,98.62) 134.63,98.39 LED1.2 ; v1(149.28,71.43) 148.89,71.04 R186.2 ; R144.2 138.44,72.25 v1(138.63,72.06) ; v1(101.1,23.14) U38.2 v1(99.01,23.14) ; D10.2 v1(108.74,22.06) ; v1(149.35,45.22) 149.26,45.12 C199.2 C196.2 ; R196.2 149.18,63.93 v1(149.28,63.83) ; J35.26 v1(115.5,66.85) 114.79,66.14 98.98,66.14 98.27,65.43 88.44,65.43 86.46,63.45 86.46,58.67 85.73,57.94 v1(76.28,57.94) ; J35.43 v1(108.7,75.31) ; C203.2 v1(97.59,19.6) ; v1(52.77,30.48) 52.27,29.97 52.27,28.07 v1(52.83,27.51) 53.53,28.22 56.96,28.22 v1(57.28,27.89) ; v1(52.77,30.48) 53.49,29.76 58.47,29.76 58.78,29.45 ; v1(52.77,30.48) 52.4,30.85 v1(52.4,32.41) v1(52.4,33.78) 52.4,36.01 54.65,38.26 114.22,38.26 114.99,37.5 114.99,36.78 v1(115.73,36.04) v1(116.69,36.04) v1(117.69,37.04) ; U21.16 146.16,76.57 v1(146.05,76.68) ; 111.89,20.06 111.94,20.11 D12.2 v1(111.94,22.06) ; J21.8 58.64,87.43 61.04,85.02 61.04,80.11 59.69,78.76 v1(59.69,78.3) ; v1(105.76,82.72) 104.99,83.49 arc(104.33,83.76) 103.66,83.49 v1(102.9,82.72) ; R121.2 v1(96.77,79.68) ; C113.2 v1(81.79,78.18) ; C21.2 v1(4.57,26.34) ; C92.2 v1(62.61,78.13) ; 97.94,75.64 97.95,75.65 Y4.2 97.12,76.75 97.1,76.73 ; v1(134.98,61.73) 135.08,61.83 U20.1 ; J35.29 v1(114.3,75.31) ; J29.5 v1(150.41,18.55) ; v1(146.69,65.88) 146.64,65.83 U35.2 ; D6.2 v1(88.62,22.13) ; v1(41.78,27.89) 41.78,44.09 v1(46.33,48.64) 46.41,48.72 96.27,48.72 97.84,50.29 98.7,50.29 ; 80.26,80.18 80.28,80.17 Y3.4 81.17,79.05 81.18,79.04 ; 99.44,80.18 99.45,80.17 Y4.4 100.2,79.05 100.2,79.04 ; 78.79,75.74 78.78,75.75 Y3.2 77.91,76.75 77.9,76.75 ; v1(121.67,55.42) 129.27,55.42 arc(129.86,55.31) 130.35,54.98 132.69,52.64 arc(133.18,52.31) 133.77,52.19 v1(146.3,52.19) J26.22 ; D19.2 v1(115.14,22.06) ; v1(135.45,73.23) 135.4,73.23 135.01,73.62 Y1.2 134.32,74.72 ; C200.2 140.6,44.59 arc(140.55,44.36) 140.42,44.17 v1(140.21,43.96) ; J35.27 v1(115.1,75.31) ; v1(0.83,72.69) 1.34,73.21 R237.2 ; C165.2 v1(110.77,79.04) ; 8.15,18.23 v1(7.19,18.23) ; C195.2 v1(149.38,39.04) ; v1(133.83,32.52) 132.35,32.52 131.71,33.16 73.05,33.16 71.28,31.39 v1(71.28,27.89) ; J29.18 152.15,25.05 arc(152.29,25.07) 152.4,25.15 v1(152.55,25.3) 152.41,25.44 arc(152.3,25.52) 152.16,25.55 J29.19 ; v1(48.41,95.79) R212.2 R216.2 51.38,95.79 v1(51.38,95.78) ; v1(126.3,65.68) 126.89,65.68 arc(127.32,65.86) 127.5,66.29 J35.4 ; 137.46,77.01 137.46,77.02 Y1.4 136.51,78.14 136.53,78.15 ; R188.1 v1(149.22,22.14) ; J29.11 v1(150.41,21.55) ; C45.2 v1(74.31,19.72) ; v1(149.35,42.22) 149.22,42.08 R198.2 ; R199.2 v1(142.62,46.15) ; C204.2 v1(100.03,25.5) ; C164.2 v1(109.75,79.04) ; 51.09,85.86 53.53,88.3 54.37,88.3 55.2,89.13 J21.5 ; R99.2 v1(71.91,66.47) ; 45.08,73.6 45.08,73.67 46.18,74.77 48.78,74.77 49.45,75.44 49.45,75.48 v1(49.5,75.54) ; C197.2 C194.2 149.2,41.06 v1(149.35,41.22) ; C201.2 139.77,16.3 v1(139.76,16.3) ; C198.2 149.24,43.1 v1(149.35,43.22) ; C109.2 v1(85.37,69.06) C102.2 ; R108.2 v1(77.6,74.09) ; R175.2 149.1,59.61 v1(149.28,59.78) ; R176.2 v1(54.11,77.86) ; C78.2 v1(62.61,76.07) ; D23.2 v1(18.16,89.96) ; v1(38.06,20.49) 37.78,20.77 J1.23 ; D26.2 v1(28.44,91.38) ; 47.93,76.37 47.93,90.29 ; C192.2 v1(140.6,66.1) ; C183.2 146.79,15.28 v1(146.76,15.3) 146.62,15.16 U37.2 ; v1(69.27,18.36) 69.65,17.98 70,17.98 70.27,18.25 C42.2 ; J35.15 v1(123.1,75.31) ; R100.2 v1(77.6,79.68) ; J26.19 v1(146.28,50.69) 133.14,50.69 arc(132.56,50.81) 132.07,51.14 129.53,53.68 arc(129.03,54.01) 128.45,54.12 121.74,54.12 v1(121.67,54.05) ; U12.3 v1(1.77,27.23) ; J26.16 133.58,49.19 ; D9.2 v1(91.82,22.13) ; C98.2 v1(96.77,78.66) ; R197.2 149.26,67.99 v1(149.28,68.01) ; v1(137.77,77.64) R143.2 C132.2 ; D7.2 v1(87.02,22.13) ; D15.1 v1(57.58,77.86) 57.58,77.95 ; J35.18 118.7,67.08 118.47,66.85 ; v1(117.69,37.04) 117.69,38.97 116.87,39.8 v1(115.6,39.8) v1(114.6,39.8) v1(113.6,39.8) 53.06,39.8 v1(50.93,37.66) ; J29.2 v1(150.41,17.05) ; C187.2 148.93,60.88 v1(149.28,61.23) ; J35.34 v1(112.3,66.85) ; R98.2 v1(73.05,66.47) ; C91.2 v1(62.61,77.09) ; D8.2 v1(90.22,22.13) ; C44.2 v1(40.38,15.34) ; J29.21 152.16,26.55 arc(152.3,26.52) 152.41,26.44 v1(152.55,26.3) 152.4,26.15 arc(152.29,26.07) 152.15,26.05 J29.20 ; C75.2 v1(76.73,66.47) ; J35.50 v1(105.9,66.85) ; C176.2 v1(140.6,69.73) ; J29.8 v1(150.41,20.05) ; C202.2 v1(97.59,20.62) ; R13.2 v1(1.96,71.41) ; R190.2 v1(149.41,16.3) ; J35.40 v1(109.9,66.85) ; C184.2 149.38,15.28 v1(149.41,15.3) ; J21.11 53.16,85.69 51.08,83.61 51.08,76.25 ; v1(149.28,70.31) 148.98,70.02 C175.2 C174.2 ; R207.2 v1(137.08,6.27) ; v1(102.07,79.07) 102.25,78.88 ; R97.2 v1(68.48,66.47) ; v1(117.98,80.36) 117.98,80.35 C163.2 ; C172.2 v1(140.6,60.12) ; C77.2 v1(77.6,77.14) ; C76.2 v1(77.6,78.66) ; C48.2 v1(78.33,18.33) ; C39.2 v1(50.92,15.35) ; J35.37 v1(111.1,75.31) ; L19.2 v1(131.33,80.91) ; D13.2 v1(113.54,22.06)
  TOP w0.381: U3.4 v1(145.6,98.47)
  TOP w0.508: 134.77,91.32 J17.77 ; J17.77 136.33,91.32 ; J17.77 135.55,89.77 ; J17.77 135.55,92.88 ; 9.27,15.7 J37.6 ; J37.6 10,14.97 ; J37.6 10,16.43 ; J37.6 10.73,15.7 ; 92.25,13.89 J12.4 ; J12.4 92.98,14.62 ; J12.4 91.52,14.62 ; J12.4 92.25,15.34 ; 26.53,58.16 SS12.1 ; SS12.1 23.26,61.44 ; SS12.1 26.53,64.72 ; SS12.1 29.81,61.44 ; SW3.3 21.28,8.11 ; SW3.3 20.4,8.99 ; SW3.3 20.4,7.23 ; SW3.3 19.52,8.11 ; 126.68,15.1 J40.3 ; J40.3 127.58,16 ; J40.3 125.78,16 ; J40.3 126.68,16.9 ; 82.53,58.16 SS13.1 ; SS13.1 82.53,64.72 ; SS13.1 79.26,61.44 ; SS13.1 85.81,61.44 ; J17.76 156.25,92.88 ; J17.76 156.25,89.77 ; J17.76 157.03,91.32 ; J17.76 155.47,91.32 ; 15.58,90.67 J39.3 ; J39.3 16.55,89 ; J39.3 17.53,90.67 ; J39.3 16.55,92.35 ; 104.8,45.81 SS5.1 ; SS5.1 107.58,48.59 ; SS5.1 102.02,48.59 ; SS9.1 149.18,8.57 ; SS9.1 142.62,8.57 ; SS9.1 145.9,11.85 ; 6.97,10.06 SW1.1 ; SW1.1 7.85,9.18 ; SW1.1 8.73,10.06 ; SW1.1 7.85,10.94 ; 129.13,7.95 J34.S1 ; J34.S1 130.36,9.18 ; J34.S1 130.36,6.72 ; 154.18,32.22 J29.31 ; J29.31 154.18,34.17 ; J29.31 155.36,33.2 ; J29.31 153,33.2 ; J20.10 105.11,88.5 ; J20.10 103.1,88.5 ; J20.10 104.1,89.5 ; J20.10 104.1,87.5 ; SS6.1 107.58,24.44 ; SS6.1 102.02,24.44 ; SS6.1 104.8,21.66 ; SS6.1 104.8,27.22 ; J26.31 155.36,58.34 ; J26.31 154.18,59.32 ; J26.31 153,58.34 ; J35.54 131.55,77.47 ; J35.54 131.55,74.51 ; J35.54 130.3,75.99 ; 124.14,15.1 J40.2 ; J40.2 124.14,16.9 ; J40.2 125.04,16 ; J40.2 123.24,16 ; 10.28,90.67 J39.2 ; J39.2 11.25,89 ; J39.2 12.23,90.67 ; J39.2 11.25,92.35 ; J34.1 120.07,9.18 ; J34.1 120.8,8.45 ; J34.1 119.34,8.45 ; J34.1 120.07,7.72 ; SW1.3 9.4,8.99 ; SW1.3 8.52,8.11 ; SW1.3 9.4,7.23 ; SW1.3 10.28,8.11 ; 116.17,7.95 J34.S2 ; J34.S2 118.63,7.95 ; J34.S2 117.4,6.72 ; J34.S2 117.4,9.18 ; J8.2 75.75,13.56 ; J8.2 74.68,12.48 ; J8.2 73.6,13.56 ; J8.2 74.68,14.64 ; J6.2 26.98,77.8 ; J6.2 26.28,78.5 ; J6.2 26.28,77.1 ; J28.6 102.95,15.34 ; J28.6 103.68,14.62 ; J28.6 102.95,13.89 ; J28.6 102.22,14.62 ; J9.4 92.25,9.44 ; J9.4 92.25,7.98 ; J9.4 91.52,8.71 ; J9.4 92.98,8.71 ; 18.85,9.18 SW3.1 ; SW3.1 17.97,10.06 ; SW3.1 19.73,10.06 ; SW3.1 18.85,10.94 ; 19.17,75.7 J16.2 ; J16.2 19.17,76.96 ; J16.2 19.79,76.33 ; 26.53,21.16 SS11.1 ; SS11.1 29.81,24.44 ; SS11.1 26.53,27.72 ; SS11.1 23.26,24.44 ; 62.17,13.56 J8.5 ; J8.5 63.25,12.48 ; J8.5 64.32,13.56 ; J8.5 63.25,14.64 ; J23.31 155.36,81.07 ; J23.31 154.18,82.05 ; J23.31 153,81.07 ; J23.32 155.36,62.27 ; J23.32 154.18,63.25 ; J23.32 153,62.27 ; J23.32 154.18,61.3 ; 2.32,12.8 J7.3 ; J7.3 3.24,13.72 ; J7.3 1.39,13.72 ; J7.3 2.32,14.65 ; 14,14.97 J37.4 ; J37.4 13.27,15.7 ; J37.4 14,16.43 ; 126.22,24.44 SS7.1 ; SS7.1 131.78,24.44 ; SS7.1 129,21.66 ; J34.7 128.42,8.45 ; J34.7 126.96,8.45 ; J34.7 127.69,9.18 ; J34.7 127.69,7.72 ; J20.4 105.11,85.5 ; J20.4 104.1,84.5 ; J20.4 104.1,86.5 ; SW2.1 13.35,10.94 ; SW2.1 14.23,10.06 ; SW2.1 12.47,10.06 ; SW2.1 13.35,9.18 ; 129,45.81 SS8.1 ; SS8.1 126.22,48.59 ; SS8.1 131.78,48.59 ; 126.35,88.15 J19.7 ; J19.7 125.62,88.88 ; J19.7 126.35,89.61 ; J19.7 127.07,88.88 ; 102.25,78.88 J35.53 102.25,73.87 ; J15.6 102.95,9.44 ; J15.6 102.22,8.71 ; J15.6 102.95,7.98 ; J15.6 103.68,8.71 ; 153,14.4 J29.32 ; J29.32 155.36,14.4 ; J29.32 154.18,15.37 ; J34.4 124.61,8.45 ; J34.4 123.88,7.72 ; J34.4 123.88,9.18 ; J34.4 123.15,8.45 ; 18,14.97 J37.2 ; J37.2 18.73,15.7 ; J37.2 18,16.43 ; 79.26,24.44 SS10.1 ; SS10.1 85.81,24.44 ; SS10.1 82.53,21.16 ; J26.32 155.36,39.54 ; J26.32 154.18,38.56 ; J26.32 153,39.54 ; J26.32 154.18,40.52 ; 14.9,7.23 SW2.3 ; SW2.3 14.9,8.99 ; SW2.3 14.02,8.11 ; SW2.3 15.78,8.11
  TOP w0.762: J18.10 79.36,84.75
  GND02 w0.508: J34.S2 118.63,7.95 ; J34.S2 117.4,6.72 ; J34.S2 116.17,7.95 ; J34.S2 117.4,9.18 ; J19.4 123.57,90.38 ; J19.4 122.85,91.11 ; J19.4 122.12,90.38 ; 102.95,7.98 J15.6 ; J15.6 103.68,8.71 ; J15.6 102.22,8.71 ; J15.6 102.95,9.44 ; 104.1,87.5 J20.10 ; J20.10 103.1,88.5 ; J20.10 105.11,88.5 ; J20.10 104.1,89.5 ; SW1.3 9.4,8.99 ; SW1.3 10.28,8.11 ; SW1.3 9.4,7.23 ; SW1.3 8.52,8.11 ; SS6.1 104.8,27.22 ; SS6.1 102.02,24.44 ; SS6.1 107.58,24.44 ; SS6.1 104.8,21.66 ; 63.25,12.48 J8.5 ; J8.5 64.32,13.56 ; J8.5 63.25,14.64 ; J8.5 62.17,13.56 ; J9.4 92.98,8.71 ; J9.4 91.52,8.71 ; J9.4 92.25,7.98 ; J9.4 92.25,9.44 ; SS8.1 131.78,48.59 ; SS8.1 126.22,48.59 ; SS8.1 129,45.81 ; SS8.1 129,51.37 ; 1.39,13.72 J7.3 ; J7.3 2.32,12.8 ; J7.3 3.24,13.72 ; J7.3 2.32,14.65 ; 56.2,91.47 J21.2 56.78,90.9 ; J16.2 19.17,76.96 ; J16.2 19.17,75.7 ; J16.2 19.79,76.33 ; 123.15,8.45 J34.4 ; J34.4 123.88,9.18 ; J34.4 124.61,8.45 ; J34.4 123.88,7.72 ; 120.07,7.72 J34.1 ; J34.1 120.07,9.18 ; J34.1 119.34,8.45 ; J34.1 120.8,8.45 ; SS7.1 131.78,24.44 ; SS7.1 126.22,24.44 ; SS7.1 129,27.22 ; SS7.1 129,21.66 ; 13.35,9.18 SW2.1 ; SW2.1 14.23,10.06 ; SW2.1 13.35,10.94 ; SW2.1 12.47,10.06 ; 91.52,14.62 J12.4 ; J12.4 92.98,14.62 ; J12.4 92.25,15.34 ; J12.4 92.25,13.89 ; SW2.3 14.9,8.99 ; SW2.3 14.02,8.11 ; SW2.3 14.9,7.23 ; SW2.3 15.78,8.11 ; J19.7 127.07,88.88 ; J19.7 126.35,89.61 ; J19.7 125.62,88.88 ; J19.7 126.35,88.15 ; 7.85,9.18 SW1.1 ; SW1.1 8.73,10.06 ; SW1.1 7.85,10.94 ; SW1.1 6.97,10.06 ; J37.2 18.73,15.7 ; J37.2 18,16.43 ; J37.2 17.27,15.7 ; J37.2 18,14.97 ; J39.3 16.55,92.35 ; J39.3 17.53,90.67 ; J39.3 15.58,90.67 ; J39.3 16.55,89 ; 11.25,89 J39.2 ; J39.2 11.25,92.35 ; J39.2 12.23,90.67 ; J39.2 10.28,90.67 ; J37.6 10,16.43 ; J37.6 10,14.97 ; J37.6 9.27,15.7 ; J37.6 10.73,15.7 ; J34.S1 130.36,9.18 ; J34.S1 131.59,7.95 ; J34.S1 130.36,6.72 ; J34.S1 129.13,7.95 ; SW3.1 18.85,10.94 ; SW3.1 18.85,9.18 ; SW3.1 19.73,10.06 ; SW3.1 17.97,10.06 ; J19.13 123.57,87.18 ; J19.13 122.12,87.18 ; J19.13 122.85,87.91 ; 73.6,13.56 J8.2 ; J8.2 74.68,12.48 ; J8.2 74.68,14.64 ; J8.2 75.75,13.56 ; SW3.3 21.28,8.11 ; SW3.3 20.4,8.99 ; SW3.3 20.4,7.23 ; SW3.3 19.52,8.11 ; 123.24,16 J40.2 ; J40.2 124.14,15.1 ; J40.2 124.14,16.9 ; J40.2 125.04,16 ; 23.76,24.44 SS11.1 ; SS11.1 29.31,24.44 ; SS11.1 26.53,21.66 ; SS11.1 26.53,27.22 ; 26.28,77.1 J6.2 ; J6.2 26.98,77.8 ; J6.2 26.28,78.5 ; SS9.1 148.68,8.57 ; SS9.1 145.9,5.8 ; SS9.1 143.12,8.57 ; SS9.1 145.9,11.35 ; SS12.1 29.31,61.44 ; SS12.1 26.53,64.22 ; SS12.1 23.76,61.44 ; SS12.1 26.53,58.66 ; 102.02,48.59 SS5.1 ; SS5.1 104.8,45.81 ; SS5.1 104.8,51.37 ; SS5.1 107.58,48.59 ; 13.27,15.7 J37.4 ; J37.4 14,16.43 ; J37.4 14.73,15.7 ; J37.4 14,14.97 ; 126.68,15.1 J40.3 ; J40.3 125.78,16 ; J40.3 127.58,16 ; J40.3 126.68,16.9 ; J19.16 126.35,86.41 ; J19.16 126.35,84.95 ; J19.16 125.62,85.68 ; J19.16 127.07,85.68 ; 127.69,7.72 J34.7 ; J34.7 128.42,8.45 ; J34.7 126.96,8.45 ; J34.7 127.69,9.18 ; SS10.1 85.31,24.44 ; SS10.1 79.76,24.44 ; SS10.1 82.53,27.22 ; SS10.1 82.53,21.66 ; J28.6 102.95,15.34 ; J28.6 103.68,14.62 ; J28.6 102.22,14.62 ; J28.6 102.95,13.89 ; SS13.1 85.31,61.44 ; SS13.1 82.53,58.66 ; SS13.1 82.53,64.22 ; SS13.1 79.76,61.44 ; 104.1,84.5 J20.4 ; J20.4 105.11,85.5 ; J20.4 104.1,86.5
  GND02 w0.762: J21.8 57.33,87.43 ; J11.10 60.59,84.75 ; J21.5 54.23,89.15 ; J21.11 54.48,85.69 ; J21.17 54.52,82.22
  ART03 w0.305: 92.23,48.77 52.09,48.77 51.78,49.08 v1(51.78,60.94) ; 87.97,41.61 43.66,41.61 41.77,43.51 v1(40.74,43.51) ; v1(62.28,65.94) 62.33,65.99 63.14,65.99 63.7,65.43 63.7,63.8 62.1,62.2 62.1,51.43 62.55,50.99 93.15,50.99 93.85,51.69 93.85,55.48 94.37,56 ; 141.78,34.49 v1(141.27,34.49) 140.26,34.49 139.9,34.13 139.9,32.74 140.23,32.41 141.21,32.41 141.25,32.46 v1(141.25,32.46) ; 113.54,29.43 113.44,29.33 113.34,29.43 ; 113.54,29.43 113.34,29.43 ; 113.54,29.43 114.34,29.43 ; 112.29,62.89 112.29,66.84 v1(112.3,66.85) ; 114.54,29.43 114.44,29.33 114.34,29.43 ; 114.54,29.43 114.34,29.43 ; 114.54,29.43 117.14,29.43 117.24,29.54 ; v1(41.48,47.42) 43.18,47.42 45.64,44.95 91.64,44.95 ; 43.9,48.73 v1(43.95,48.68) v1(46.43,46.2) 46.45,46.18 74.29,46.18 ; v1(109.72,70.61) 109.72,63.67 109.3,63.24 102.49,63.24 ; 17.24,44.66 16.76,45.13 v1(16.76,53.29) v1(16.76,56.43) v1(16.76,65.88) ; 140.08,29.16 139.37,29.87 134.54,29.87 133.83,30.58 v1(133.83,32.52) 133.83,33.76 v1(133.86,33.79) 134.33,34.26 135.71,34.26 136.23,33.75 ; 86.06,39.01 45.8,39.01 v1(45.8,39.01) ; v1(132.22,39.64) 131.55,38.96 131.55,36.75 129.93,35.13 129.93,31.9 129,30.98 69.6,30.98 ; 140.72,16.84 v1(145.23,16.84) v1(146.76,15.3) ; 121.72,52.83 121.72,52.7 v1(121.69,52.68) ; 130.71,29.54 131.37,30.2 131.37,34.46 133.43,36.52 136.77,36.52 v1(138.52,38.27) ; v1(122.76,41.7) 122.76,39.09 ; v1(101.15,48.52) v1(101.15,47.52) v1(101.15,46.53) ; 118.24,29.54 117.64,29.54 ; 118.24,29.54 118.64,29.54 v1(118.44,29.33) 118.24,29.54 ; 117.64,29.54 v1(117.44,29.33) 117.24,29.54 ; 117.64,29.54 117.24,29.54 ; v1(129.25,39.64) 129.64,39.25 129.64,36.93 128.88,36.17 v1(128.14,36.17) ; v1(42.16,45.92) 42.17,45.92 42.87,45.92 44.93,43.86 90.57,43.86 91.26,43.18 ; 113.34,29.43 75.03,29.43 75.02,29.45 74.55,29.45 74.54,29.43 74.03,29.43 74.02,29.45 73.55,29.45 73.54,29.43 v1(69.29,29.43) 69.16,29.43 66.22,32.38 51.87,32.38 50.98,31.49 50.98,25.08 v1(50.78,24.89) ; v1(18.26,62.53) 18.34,62.46 18.34,51.55 ; 42.36,44.66 44.36,42.65 89.22,42.65 ; v1(87.83,39.77) 87.29,40.31 46.25,40.31 ; 21.34,53.18 21.34,67.79 v1(21.23,67.89) ; v1(43.78,24.89) 43.78,27.95 43.74,27.99 43.74,28.44 43.78,28.48 43.78,28.95 43.74,28.99 43.74,29.44 43.78,29.48 43.78,29.95 43.74,29.99 43.74,30.44 43.78,30.48 43.78,32.73 v1(48.29,37.23) 48.74,37.69 69.27,37.69 71.77,35.19 121.77,35.19 v1(123.64,37.05) ; 48.01,60.67 v1(48.28,60.94) ; v1(19.89,62.73) 19.89,52.04 ; 27.49,45.92 v1(27.46,45.89) ; v1(48.78,24.89) 49.15,25.26 49.15,31.77 51.17,33.78 v1(66.75,33.78) ; 136.35,56.58 v1(136.43,56.66) ; v1(39.78,32.89) v1(39.78,31.89) v1(39.78,30.89) v1(39.78,29.89) ; v1(115.6,58.09) v1(114.02,58.09)
  ART03 w0.508: 82.53,58.66 SS13.1 ; SS13.1 79.76,61.44 ; SS13.1 82.53,64.22 ; SS13.1 85.31,61.44 ; SS10.1 82.53,27.22 ; SS10.1 79.76,24.44 ; SS10.1 85.31,24.44 ; J37.2 18,16.43 ; J37.2 17.27,15.7 ; J37.2 18,14.97 ; J37.2 18.73,15.7 ; 104.8,21.66 SS6.1 ; SS6.1 104.8,27.22 ; SS6.1 107.58,24.44 ; SS6.1 102.02,24.44 ; 2.32,12.8 J7.3 ; J7.3 1.39,13.72 ; J7.3 2.32,14.65 ; J7.3 3.24,13.72 ; 126.22,24.44 SS7.1 ; SS7.1 129,27.22 ; SS7.1 129,21.66 ; SS7.1 131.78,24.44 ; SW1.3 9.4,8.99 ; SW1.3 8.52,8.11 ; SW1.3 9.4,7.23 ; SW1.3 10.28,8.11 ; 11.25,89 J39.2 ; J39.2 10.28,90.67 ; J39.2 12.23,90.67 ; J39.2 11.25,92.35 ; J16.2 19.79,76.33 ; J16.2 19.17,76.96 ; J16.2 19.17,75.7 ; J39.3 16.55,92.35 ; J39.3 17.53,90.67 ; J39.3 16.55,89 ; J39.3 15.58,90.67 ; J20.4 105.11,85.5 ; J20.4 104.1,84.5 ; J20.4 104.1,86.5 ; SW3.1 19.73,10.06 ; SW3.1 18.85,10.94 ; SW3.1 17.97,10.06 ; SW3.1 18.85,9.18 ; 7.85,9.18 SW1.1 ; SW1.1 8.73,10.06 ; SW1.1 6.97,10.06 ; SW1.1 7.85,10.94 ; J37.4 14.73,15.7 ; J37.4 14,14.97 ; J37.4 14,16.43 ; J37.4 13.27,15.7 ; 104.1,87.5 J20.10 ; J20.10 104.1,89.5 ; J20.10 103.1,88.5 ; J20.10 105.11,88.5 ; J15.6 103.68,8.71 ; J15.6 102.22,8.71 ; J15.6 102.95,7.98 ; SW3.3 21.28,8.11 ; SW3.3 20.4,7.23 ; SW3.3 20.4,8.99 ; SW3.3 19.52,8.11 ; 122.12,90.38 J19.4 ; J19.4 122.85,91.11 ; J19.4 123.57,90.38 ; J6.2 26.28,78.5 ; J6.2 26.28,77.1 ; J6.2 26.98,77.8 ; SS12.1 29.31,61.44 ; SS12.1 26.53,64.22 ; SS12.1 26.53,58.66 ; SS12.1 23.76,61.44 ; 120.07,7.72 J34.1 ; J34.1 120.8,8.45 ; J34.1 119.34,8.45 ; J34.1 120.07,9.18 ; J12.4 92.25,15.34 ; J12.4 91.52,14.62 ; J12.4 92.25,13.89 ; J12.4 92.98,14.62 ; SW2.3 15.78,8.11 ; SW2.3 14.9,7.23 ; SW2.3 14.02,8.11 ; SW2.3 14.9,8.99 ; 145.9,5.8 SS9.1 ; SS9.1 148.68,8.57 ; SS9.1 143.12,8.57 ; SS9.1 145.9,11.35 ; 104.8,45.81 SS5.1 ; SS5.1 102.02,48.59 ; SS5.1 104.8,51.37 ; SS5.1 107.58,48.59 ; 125.78,16 J40.3 127.58,16 ; 102.95,13.89 J28.6 ; J28.6 102.22,14.62 ; J28.6 102.95,15.34 ; J28.6 103.68,14.62 ; 130.36,6.72 J34.S1 ; J34.S1 130.36,9.18 ; J34.S1 131.59,7.95 ; J34.S1 129.13,7.95 ; 73.6,13.56 J8.2 ; J8.2 74.68,14.64 ; J8.2 74.68,12.48 ; J8.2 75.75,13.56 ; J34.7 128.42,8.45 ; J34.7 127.69,7.72 ; J34.7 126.96,8.45 ; J34.7 127.69,9.18 ; J34.S2 118.63,7.95 ; J34.S2 116.17,7.95 ; J34.S2 117.4,9.18 ; J34.S2 117.4,6.72 ; SW2.1 13.35,10.94 ; SW2.1 13.35,9.18 ; SW2.1 12.47,10.06 ; SW2.1 14.23,10.06 ; SS11.1 26.53,27.22 ; SS11.1 29.31,24.44 ; SS11.1 26.53,21.66 ; SS11.1 23.76,24.44 ; J19.7 127.07,88.88 ; J19.7 126.35,88.15 ; J19.7 126.35,89.61 ; J19.7 125.62,88.88 ; 9.27,15.7 J37.6 ; J37.6 10,16.43 ; J37.6 10,14.97 ; J37.6 10.73,15.7 ; SS8.1 129,51.37 ; SS8.1 126.22,48.59 ; SS8.1 129,45.81 ; SS8.1 131.78,48.59 ; J8.5 63.25,14.64 ; J8.5 64.32,13.56 ; J8.5 62.17,13.56 ; J8.5 63.25,12.48 ; 126.35,84.95 J19.16 ; J19.16 127.07,85.68 ; J19.16 125.62,85.68 ; J19.16 126.35,86.41 ; J34.4 124.61,8.45 ; J34.4 123.15,8.45 ; J34.4 123.88,7.72 ; J34.4 123.88,9.18 ; 125.04,16 J40.2 123.24,16 ; J19.13 122.85,87.91 ; J19.13 122.12,87.18 ; J19.13 123.57,87.18
  ART03 w0.762: J18.10 78.6,84.75 ; J11.10 60.9,84.75
  ART04 w0.305: v1(115.97,61.83) v1(115.97,60.83) 115.6,60.45 v1(115.6,58.09) v1(115.6,56.77) 115.6,55.5 v1(115.65,55.44) v1(115.65,53.97)
  ART04 w0.508: 82.53,58.66 SS13.1 ; SS13.1 82.53,64.22 ; SS13.1 85.31,61.44 ; SS9.1 148.68,8.57 ; SS9.1 145.9,11.35 ; SS9.1 145.9,5.8 ; SS9.1 143.12,8.57 ; SS10.1 82.53,27.22 ; SS10.1 82.53,21.66 ; SS10.1 85.31,24.44 ; SS10.1 79.76,24.44 ; 2.32,12.8 J7.3 ; J7.3 1.39,13.72 ; J7.3 2.32,14.65 ; J7.3 3.24,13.72 ; J39.2 12.23,90.67 ; J39.2 11.25,89 ; J39.2 11.25,92.35 ; J39.2 10.28,90.67 ; SW1.1 7.85,10.94 ; SW1.1 6.97,10.06 ; SW1.1 7.85,9.18 ; SW1.1 8.73,10.06 ; 16.55,89 J39.3 ; J39.3 15.58,90.67 ; J39.3 17.53,90.67 ; J39.3 16.55,92.35
  BOTTOM w0.254: 105.8,77.77 115.1,77.77 116.12,76.75 119.71,76.75 120.09,76.37 v1(120.09,75.33) ; 96.85,44.19 100.71,44.19 101.14,44.62 101.14,46.53 v1(101.15,46.53)
  BOTTOM w0.305: D28.1 56.94,98.62 v1(56.94,99.17) ; C117.2 v1(141.73,86.15) ; C153.2 v1(102.23,96.62) ; C81.2 71.27,75.45 v1(70.74,75.98) ; C81.2 C73.2 ; C81.2 C90.2 ; 114.14,69.61 114.14,75.15 v1(114.3,75.31) ; 39.78,27.93 v1(39.78,27.89) ; v1(0.83,41.21) 1.48,40.56 C19.2 ; J24.24 v1(150.26,80.98) ; R75.2 136.77,60.88 136.13,61.52 v1(136.13,62.73) ; v1(52.8,16.06) R41.2 v1(53.59,15.34) ; R177.2 53.15,85.41 v1(53.16,85.42) ; v1(71.74,75.98) 72.29,75.43 C90.2 ; C90.2 C89.2 ; C95.2 C94.2 ; C95.2 C103.2 ; C95.2 89.43,75.62 v1(89.02,76.03) ; C94.2 C111.2 ; C94.2 90.45,75.6 v1(90.02,76.03) ; v1(6.33,66.54) 6.26,66.47 R12.2 ; v1(140.72,86.15) C121.2 C120.2 ; R162.2 25.45,89.95 v1(24.61,89.12) ; v1(101.15,48.52) 101.66,49.02 v1(101.66,50.26) ; C169.2 146.36,52.24 v1(146.3,52.19) ; U17.4 14.1,81.01 v1(13.79,81.32) ; C38.2 v1(22.82,18.09) ; 121.12,36.29 121.11,36.28 121.11,29.09 119.02,27 119.02,21.32 118.34,20.63 118.34,14.54 ; v1(32.23,90.39) 31.8,89.95 C150.2 ; v1(69.27,18.36) 69.26,18.36 U11.15 ; D2.1 v1(12.09,21.15) ; v1(152.7,52.78) J22.4 ; v1(134.98,62.73) 134.67,63.04 C34.2 ; U10.8 v1(17.53,22.5) 16.86,23.17 C41.2 ; C18.2 1.44,70.28 v1(0.83,70.88) ; C144.2 v1(125.91,94.61) ; C28.2 v1(138.46,23.52) C30.2 ; C111.2 C110.2 ; C111.2 91.47,75.59 v1(91.02,76.03) ; 51.49,20.49 v1(50.14,20.49) 49.7,20.94 R40.2 ; C73.2 70.26,75.47 v1(69.74,75.98) ; C73.2 C83.2 ; U25.2 26.72,86.69 v1(27.94,86.69) ; v1(6.09,38.62) 6.09,39.2 5.75,39.54 R8.2 ; v1(77.6,77.14) 77.45,77.28 R106.2 ; v1(138.52,38.27) C47.2 139.2,38.54 139.5,38.84 arc(139.65,39.06) 139.7,39.32 U15.2 ; v1(70.74,76.98) v1(71.74,76.98) 72.27,76.98 C84.2 C93.2 ; v1(0.83,56.45) 0.98,56.31 C9.2 ; C146.2 v1(120.24,98.6) ; v1(149.26,80.98) 149.79,80.45 151.4,80.45 J24.23 ; v1(145.71,38.24) 144.91,39.04 U14.5 ; v1(146.69,69.72) 146.89,69.52 C173.2 ; C57.2 v1(130.04,71.24) ; v1(73.05,66.47) 73.05,67.26 74.03,68.24 C82.2 C85.2 ; v1(23.22,84.37) 23.29,84.3 D20.2 ; v1(7.19,21.21) 7.43,20.96 D37.2 ; v1(115.1,75.31) 115.47,74.94 C56.2 ; 122.33,95.36 121.5,95.36 v1(121.49,95.35) ; 115.67,36.04 v1(115.73,36.04) v1(116.69,36.04) v1(117.69,37.04) ; C104.2 C105.2 94.88,68.24 95.88,67.24 C97.2 v1(95.91,66.47) ; v1(89.02,77.03) 89.18,77.2 C107.2 C108.2 ; C66.2 v1(23.22,85.77) C151.2 C152.2 ; 89.28,99.12 v1(89.23,99.17) ; v1(20.29,79.07) 20.29,79.07 D24.1 20.29,80.79 v1(20.29,80.79) 20.83,81.33 20.96,81.33 ; v1(123.18,26.29) 122.68,25.78 C207.2 123.07,23.15 C208.2 ; v1(133.71,96.24) C148.2 C149.2 ; C168.2 v1(58.13,97.7) ; C134.2 C135.2 146.13,76.75 v1(146.05,76.68) ; 119.74,29.65 117.83,27.74 117.83,22.07 117.12,21.36 117.12,19.45 v1(116.59,18.92) 116.59,18.87 117.09,18.36 117.09,13.38 v1(116.59,12.87) ; R69.2 39.15,23.26 v1(39.78,23.89) ; v1(31.39,21.46) 31.61,21.25 C37.2 ; v1(125.09,97.48) 125.08,97.49 ; v1(26.49,17.95) 26.39,18.06 U9.2 ; v1(69.74,76.98) 70,77.25 C86.2 C87.2 ; v1(99.01,23.14) 98.45,23.14 98.31,23.28 R192.2 ; J22.24 150.32,62.78 v1(150.28,62.83) ; C40.2 v1(22.34,19.77) ; C155.2 v1(100.47,99.17) ; C154.2 v1(102.23,98.56) ; D34.2 29.57,91.51 v1(29.44,91.38) ; v1(39.4,20.49) 39.5,20.6 U13.5 ; v1(105.9,66.85) 106.16,66.59 C55.2 ; C71.2 135.64,69.52 v1(135.45,69.72) ; C137.2 v1(113.02,94.56) ; C10.2 0.94,54.53 v1(0.83,54.64) ; C213.2 v1(40.21,90.47) ; C149.2 v1(132.72,96.24) ; C149.2 132.68,96.99 132.18,97.49 U26.2 ; C6.2 0.95,42.34 v1(0.83,42.21) ; v1(18.16,90.96) v1(18.16,89.96) v1(18.16,88.96) v1(19.16,88.96) 19.47,88.65 L20.2 20.12,88.74 21.34,89.96 R159.2 ; 116.38,94.92 116.38,94.92 Y2.2 115.43,93.78 115.44,93.77 ; C63.2 v1(11.17,24.17) ; C65.2 v1(13.69,24.87) ; D1.1 v1(11.17,21.92) ; C119.2 C118.2 C122.2 v1(137.67,80.77) ; D33.2 31.07,98.97 v1(31.27,99.17) ; C136.2 v1(149.25,79.8) ; v1(139.43,57.54) 139.43,58.25 139.09,58.59 C79.2 137.79,58.89 C80.2 ; R112.2 R142.2 143.76,80.56 144.2,80.13 v1(144.37,80.13) ; C51.2 136.02,40.81 ; v1(108.47,99.17) 108.07,98.77 C157.2 ; L2.2 v1(13.97,96.29) ; C64.2 v1(12.79,24.17) ; C16.2 v1(149.35,95.83) ; v1(90.02,77.03) v1(91.02,77.03) 91.04,77.01 C106.2 C112.2 C100.2 ; C27.2 1.12,68.5 0.81,68.2 v1(0.81,67.48) ; D3.1 v1(13.69,21.15) ; 118.01,61.86 v1(117.98,61.83) ; U9.8 28.67,16.79 v1(28.57,16.68) ; C147.2 v1(127.41,94.61) ; C116.2 C115.2 137.93,77.64 v1(137.77,77.64) ; C75.2 v1(76.73,66.47) ; C35.2 134.68,62.02 v1(134.98,61.73) ; C159.2 v1(10.55,74.49) ; v1(144.59,25.71) J41.6 v1(142.2,25.71) ; R79.2 R82.2 146.05,80.44 146.35,80.13 v1(146.63,80.13) ; R135.2 v1(96.77,77.14) ; C52.2 v1(136.02,38.27) ; v1(150.28,61.23) 150.33,61.28 ; Y2.4 v1(113.03,97.22) 112.66,97.59 C138.2 ; J40.2 122.92,14.78 120.04,14.78 119.63,15.19 v1(119.63,18.92) 119.63,20.32 120.09,20.77 120.09,26.08 122.71,28.7 ; R163.2 v1(103.01,92.64) ; U6.4 v1(56.18,20.49) ; 129.24,95.36 v1(129.24,94.51) ; v1(149.28,62.83) 149.82,62.28 J22.23 ; C156.2 v1(105.09,99.17) ; C158.2 v1(112.88,98.56) ; v1(43.05,15.35) 43.05,16.06 v1(42.35,16.06) ; C15.2 v1(148.21,95.83) ; U10.2 v1(18.8,27.66)
  BOTTOM w0.508: SW2.3 15.78,8.11 ; SW2.3 14.02,8.11 ; SW2.3 14.9,8.99 ; SW2.3 14.9,7.23 ; J41.13 143.92,16.68 ; J41.13 142.86,15.62 ; J41.13 144.99,15.62 ; J41.13 143.92,14.55 ; J8.5 63.25,14.64 ; J8.5 64.32,13.56 ; J8.5 63.25,12.48 ; J8.5 62.17,13.56 ; 129,45.81 SS8.1 ; SS8.1 126.22,48.59 ; SS8.1 131.78,48.59 ; SS8.1 129,51.37 ; U14.9 145.65,34.06 ; U14.9 143.19,34.06 ; U14.9 144.42,34.74 ; U14.9 144.42,33.38 ; J34.7 128.42,8.45 ; J34.7 127.69,7.72 ; J34.7 127.69,9.18 ; J34.7 126.96,8.45 ; C145.2 125.15,97.54 v1(125.09,97.48) ; 143.12,8.57 SS9.1 ; SS9.1 145.9,5.8 ; SS9.1 145.9,11.35 ; SS9.1 148.68,8.57 ; 153.52,13.78 J41.12 ; J41.12 154.91,14.71 ; J41.12 152.14,14.71 ; J41.12 153.52,15.65 ; J7.3 2.32,14.65 ; J7.3 3.24,13.72 ; J7.3 1.39,13.72 ; J7.3 2.32,12.8 ; 92.25,7.98 J9.4 ; J9.4 92.98,8.71 ; J9.4 92.25,9.44 ; J9.4 91.52,8.71 ; 104.8,21.66 SS6.1 ; SS6.1 102.02,24.44 ; SS6.1 107.58,24.44 ; SS6.1 104.8,27.22 ; 126.35,88.15 J19.7 ; J19.7 125.62,88.88 ; J19.7 126.35,89.61 ; J19.7 127.07,88.88 ; 56.78,90.9 J21.2 56.2,91.47 ; J40.3 126.68,16.9 ; J40.3 127.58,16 ; J40.3 126.68,15.1 ; J40.3 125.78,16 ; J34.4 124.61,8.45 ; J34.4 123.15,8.45 ; J34.4 123.88,7.72 ; J34.4 123.88,9.18 ; 125.08,97.49 U24.2 ; SS5.1 104.8,51.37 ; SS5.1 102.02,48.59 ; SS5.1 104.8,45.81 ; 104.1,87.5 J20.10 ; J20.10 103.1,88.5 ; J20.10 104.1,89.5 ; SW3.1 18.85,10.94 ; SW3.1 19.73,10.06 ; SW3.1 17.97,10.06 ; SW3.1 18.85,9.18 ; 122.12,87.18 J19.13 ; J19.13 122.85,87.91 ; J19.13 123.57,87.18 ; 73.6,13.56 J8.2 ; J8.2 74.68,14.64 ; J8.2 74.68,12.48 ; J8.2 75.75,13.56 ; 18,14.97 J37.2 ; J37.2 17.27,15.7 ; J37.2 18.73,15.7 ; J37.2 18,16.43 ; 10,14.97 J37.6 ; J37.6 9.27,15.7 ; J37.6 10,16.43 ; 152.95,82.68 J24.25 ; J24.25 155.31,82.68 ; J24.25 154.13,81.7 ; J24.25 154.13,83.66 ; SS10.1 82.53,27.22 ; SS10.1 82.53,21.66 ; SS10.1 79.76,24.44 ; SS10.1 85.31,24.44 ; J40.2 124.14,16.9 ; J40.2 124.14,15.1 ; J40.2 125.04,16 ; J40.2 123.24,16 ; 14,14.97 J37.4 14,16.43 ; SW1.1 8.73,10.06 ; SW1.1 7.85,10.94 ; SW1.1 6.97,10.06 ; SW1.1 7.85,9.18 ; 152.95,64.48 J22.25 ; J22.25 154.13,65.46 ; J22.25 154.13,63.5 ; J22.25 155.31,64.48 ; J16.2 19.79,76.33 ; J16.2 19.17,76.96 ; J16.2 19.17,75.7 ; J34.S2 117.4,9.18 ; J34.S2 118.63,7.95 ; J34.S2 116.17,7.95 ; J34.S2 117.4,6.72 ; 26.53,58.66 SS12.1 ; SS12.1 26.53,64.22 ; SS12.1 29.31,61.44 ; SS12.1 23.76,61.44 ; 20.4,7.23 SW3.3 ; SW3.3 21.28,8.11 ; SW3.3 20.4,8.99 ; SW3.3 19.52,8.11 ; J6.2 26.98,77.8 ; J6.2 26.28,78.5 ; J6.2 26.28,77.1 ; 26.53,21.66 SS11.1 ; SS11.1 26.53,27.22 ; SS11.1 29.31,24.44 ; SS11.1 23.76,24.44 ; 153.52,29.28 J41.11 ; J41.11 154.91,30.22 ; J41.11 153.52,31.15 ; 9.4,7.23 SW1.3 ; SW1.3 9.4,8.99 ; SW1.3 8.52,8.11 ; SW1.3 10.28,8.11 ; 126.35,84.95 J19.16 ; J19.16 126.35,86.41 ; J19.16 125.62,85.68 ; J19.16 127.07,85.68 ; J34.1 120.8,8.45 ; J34.1 120.07,9.18 ; J34.1 119.34,8.45 ; J34.1 120.07,7.72 ; 152.95,67.78 J24.26 ; J24.26 155.31,67.78 ; J24.26 154.13,66.8 ; J39.2 12.23,90.67 ; J39.2 10.28,90.67 ; J39.2 11.25,92.35 ; J39.2 11.25,89 ; 92.25,13.89 J12.4 ; J12.4 92.25,15.34 ; J12.4 91.52,14.62 ; J12.4 92.98,14.62 ; 156.42,33.38 U14.11 ; U14.11 155.19,34.06 ; U14.11 156.42,34.74 ; J22.26 154.13,50.56 ; J22.26 155.31,49.58 ; J22.26 152.95,49.58 ; 144.42,46.38 U14.8 ; U14.8 143.19,47.06 ; U14.8 145.65,47.06 ; J39.3 16.55,92.35 ; J39.3 16.55,89 ; J39.3 15.58,90.67 ; J39.3 17.53,90.67 ; 126.22,24.44 SS7.1 ; SS7.1 131.78,24.44 ; SS7.1 129,27.22 ; SS7.1 129,21.66 ; 102.95,7.98 J15.6 ; J15.6 103.68,8.71 ; J15.6 102.22,8.71 ; J15.6 102.95,9.44 ; 13.35,9.18 SW2.1 ; SW2.1 12.47,10.06 ; SW2.1 14.23,10.06 ; 82.53,58.66 SS13.1 ; SS13.1 82.53,64.22 ; SS13.1 79.76,61.44 ; 122.12,90.38 J19.4 ; J19.4 122.85,91.11 ; J19.4 123.57,90.38 ; 129.13,7.95 J34.S1 ; J34.S1 131.59,7.95 ; J34.S1 130.36,6.72 ; J34.S1 130.36,9.18 ; 155.19,47.06 U14.10 156.42,46.38 ; 102.95,13.89 J28.6 ; J28.6 103.68,14.62 ; J28.6 102.95,15.34 ; J28.6 102.22,14.62 ; 104.1,86.5 J20.4 105.11,85.5 ; J41.10 144.99,30.22 ; J41.10 143.92,30.99 ; J41.10 142.86,30.22
  BOTTOM w0.762: J11.10 60.58,84.75 ; J18.10 79.34,84.75
  BOTTOM w1.016: C167.2 87.17,90.08 R183.2 R131.2 86.83,92.01 85.22,93.62 79.73,93.62 78.87,94.48 78.87,97.89 ; C166.2 68.83,90.08 R173.2 R27.2 67.37,92.01 65.79,93.6 61.32,93.6
  vias: v1(0.83,92.74) v1(0.83,88.93) v1(0.83,85.12) v1(0.83,81.31) v1(0.83,77.5) v1(0.83,73.69) v1(0.83,69.88) v1(0.83,66.07) v1(0.83,62.26) v1(0.83,58.45) v1(0.83,55.45) v1(0.83,50.83) v1(0.83,47.02) v1(0.83,44.21) v1(0.83,39.4) v1(0.83,35.59) v1(0.83,31.78) v1(0.83,27.97) v1(0.83,24.16) v1(0.83,20.35) v1(0.83,16.54) v1(0.83,12.73) v1(3.6,21.97) v1(4.6,21.97) v1(5.55,79.8) v1(6.12,52.57) v1(6.12,51.57) v1(6.12,50.57) v1(6.09,37.62) v1(6.09,36.62) v1(6.33,65.54) v1(6.33,64.54) v1(6.55,74.49) v1(6.55,85.21) v1(6.55,84.21) v1(6.55,79.8) v1(6.55,78.8) v1(6.65,23.08) v1(6.86,5.83) v1(7.12,52.57) v1(7.12,51.57) v1(7.12,50.57) v1(7.09,38.62) v1(7.09,37.62) v1(7.09,36.62) v1(7.33,66.54) v1(7.33,65.54) v1(7.33,64.54) v1(7.55,74.49) v1(7.55,79.8) v1(7.76,85.21) v1(8.56,74.47) v1(8.76,85.21) v1(9.42,35.35) v1(9.55,74.49) v1(10.67,5.83) v1(11.42,35.35) v1(11.76,85.21) v1(12.42,35.35) v1(12.42,34.35) v1(12.42,33.35) v1(12.42,32.35) v1(12.42,31.35) v1(12.42,30.35) v1(12.42,29.35) v1(12.42,28.35) v1(12.42,27.35) v1(12.76,85.21) v1(12.97,96.29) v1(13.79,82.32) v1(14.12,69.9) v1(14.12,68.9) v1(14.12,67.9) v1(14.48,5.83) v1(14.97,97.29) v1(14.97,96.29) v1(15.24,65.53) v1(15.24,64.53) v1(15.24,63.53) v1(15.24,62.53) v1(15.24,57.02) v1(15.24,56.02) v1(15.24,55.02) v1(15.24,54.02) v1(15.24,53.02) v1(15.24,52.02) v1(15.24,51.02) v1(15.79,82.32) v1(15.79,81.32) v1(16.41,70.05) v1(16.79,82.32) v1(16.79,81.32) v1(16.79,64.88) v1(16.79,63.88) v1(16.79,62.88) v1(16.79,61.88) v1(18.08,72.16) v1(18.26,67.53) v1(18.26,66.53) v1(18.26,65.53) v1(18.26,64.53) v1(18.26,63.53) v1(18.26,57.93) v1(18.31,55.09) v1(18.29,5.83) v1(18.44,92.48) v1(18.53,22.5) v1(19.08,72.16) v1(19.53,22.5) v1(19.63,70.68) v1(19.8,27.66) v1(19.91,69.26) v1(19.89,65.73) v1(19.89,64.73) v1(19.89,63.73) v1(20.08,72.16) v1(20.63,70.68) v1(20.91,69.26) v1(21.08,72.16) v1(21.82,18.09) v1(22.1,5.83) v1(22.34,21.77) v1(22.34,20.77) v1(22.65,99.17) v1(22.56,95.17) v1(23.11,58.3) v1(23.11,57.3) v1(23.11,56.3) v1(23.11,55.3) v1(23.11,54.3) v1(23.22,83.37) v1(23.19,69.26) v1(23.19,67.89) v1(23.96,66.19) v1(24.19,70.66) v1(24.19,69.26) v1(24.19,67.89) v1(24.96,66.19) v1(25.2,73.61) v1(25.2,72.06) v1(25.19,70.66) v1(25.19,69.26) v1(25.19,67.89) v1(25.73,95.17) v1(25.83,47.44) v1(25.91,5.83) v1(25.96,66.19) v1(26.2,73.61) v1(26.2,72.06) v1(26.19,70.66) v1(26.19,69.26) v1(26.19,67.89) v1(26.46,99.17) v1(26.57,50.49) v1(26.82,54.94) v1(26.77,48.74) v1(26.95,19.94) v1(26.96,66.19) v1(27.2,73.61) v1(27.2,72.06) v1(27.19,70.66) v1(27.19,69.26) v1(27.19,67.89) v1(27.44,91.38) v1(27.46,47.42) v1(27.49,17.95) v1(27.58,75.51) v1(27.57,50.49) v1(27.57,16.68) v1(27.94,85.69) v1(27.95,19.94) v1(27.96,66.19) v1(28.19,70.66) v1(28.19,69.26) v1(28.19,67.89) v1(28.49,17.95) v1(28.57,50.49) v1(28.94,86.69) v1(29.21,48.74) v1(29.24,47.39) v1(29.24,45.92) v1(29.54,55.94) v1(29.54,54.94) v1(29.54,53.94) v1(29.57,50.49) v1(29.72,5.83) v1(30.27,99.17) v1(30.39,22.46) v1(30.39,21.46) v1(31.09,84.1) v1(31.24,45.89) v1(31.19,43.51) v1(31.7,53.95) v1(31.88,48.74) v1(32.13,84.1) v1(32.19,43.51) v1(32.54,70.71) v1(32.54,69.29) v1(32.54,67.86) v1(33.16,73.63) v1(33.19,43.51) v1(33.5,45.89) v1(33.53,5.83) v1(34.04,34.89) v1(34.04,33.89) v1(34.04,32.89) v1(34.04,31.89) v1(34.04,30.89) v1(34.04,29.89) v1(34.04,28.89) v1(34.08,99.17) v1(34.19,43.51) v1(34.62,80.06) v1(35.28,65.35) v1(35.62,80.06) v1(35.64,67.89) v1(35.86,69.29) v1(36.04,43.46) v1(36.04,42.46) v1(36.04,28.89) v1(36.14,45.92) v1(36.18,73.63) v1(36.47,97.7) v1(36.62,80.06) v1(36.78,54.94) v1(36.78,53.94) v1(37.34,5.83) v1(37.47,97.7) v1(37.53,77.86) v1(37.89,99.17) v1(38.28,31.89) v1(38.28,30.89) v1(38.28,29.89) v1(38.28,28.89) v1(38.28,27.89) v1(38.37,16.68) v1(38.47,97.7) v1(39.24,70.3) v1(39.29,67.99) v1(39.27,53.49) v1(39.47,47.42) v1(39.85,41.14) v1(39.85,38.91) v1(40.14,97.7) v1(40.11,45.94) v1(40.05,10.26) v1(40.78,60.94) v1(40.82,52.47) v1(40.78,24.89) v1(41.14,97.7) v1(41.12,79.78) v1(41.05,10.26) v1(41.15,5.83) v1(41.3,73.17) v1(41.63,36.5) v1(41.7,99.17) v1(41.71,41.12) v1(41.71,38.91) v1(41.78,70.43) v1(41.81,66.97) v1(41.81,65.97) v1(41.81,64.97) v1(41.78,61.94) v1(41.82,52.47) v1(42.14,97.7) v1(42.05,10.26) v1(42.34,87.68) v1(42.27,54.73) v1(42.82,52.47) v1(43.34,87.68) v1(43.54,71.75) v1(43.82,52.47) v1(44.28,61.94) v1(44.27,39.01) v1(44.27,36.56) v1(44.27,35.56) v1(44.27,33.22) v1(44.27,32.22) v1(44.27,31.22) v1(44.27,30.22) v1(44.27,29.22) v1(44.27,28.22) v1(44.28,20.99) v1(44.78,56) v1(44.82,52.47) v1(45,54.73) v1(44.96,5.83) v1(45.16,47.52) v1(45.28,60.94) v1(45.51,99.17) v1(45.78,61.94) v1(45.8,37.01) v1(45.8,36.01) v1(46.08,71.6) v1(46.08,70.6) v1(47.47,86.86) v1(47.47,85.86) v1(47.47,84.86) v1(48.28,61.94) v1(48.79,71.72) v1(48.79,70.72) v1(48.79,69.72) v1(48.77,5.83) v1(49.32,99.17) v1(49.5,78.41) v1(49.83,54.91) v1(49.81,40.33) v1(50.8,28.14) v1(51.05,8.48) v1(51.59,86.97) v1(51.72,69.72) v1(51.78,61.94) v1(52.05,8.48) v1(52.25,39.01) v1(52.38,95.78) v1(52.53,48.74) v1(52.58,5.83) v1(53.13,99.17) v1(53.12,59.75) v1(53.05,8.48) v1(53.16,84.42) v1(53.4,33.78) v1(53.5,75.56) v1(53.53,48.74) v1(53.47,37.69) v1(53.76,55.53) v1(54.04,59.75) v1(54.03,31.49) v1(54.05,8.48) v1(54.36,58.88) v1(54.53,48.74) v1(54.74,37.69) v1(54.76,55.53) v1(55.18,21.49) v1(55.18,20.49) v1(55.63,77.85) v1(56.18,21.49) v1(56.39,5.83) v1(57.28,56.94) v1(57.28,55.94) v1(57.28,54.94) v1(57.33,37.69) v1(57.48,69.77) v1(58.78,27.89) v1(59.54,37.69) v1(59.49,33.78) v1(59.66,75.51) v1(59.78,23.89) v1(60.17,71.29) v1(60.2,5.83) v1(60.4,69.77) v1(61.04,82.75) v1(61.17,71.29) v1(61.61,76.07) v1(61.61,75.08) v1(61.87,37.69) v1(62.18,69.16) v1(63.28,57.94) v1(63.78,23.89) v1(64.01,5.83) v1(64.29,80.56) v1(64.44,33.78) v1(65.46,80.56) v1(66.78,57.94) v1(66.78,31.8) v1(67.03,21) v1(67.82,5.83) v1(68.33,79.52) v1(69.29,31.29) v1(69.29,28.11) v1(69.78,60.94) v1(70.78,60.94) v1(70.78,23.89) v1(71.63,5.83) v1(72.78,60.94) v1(72.78,48.74) v1(73.61,80.01) v1(74.28,60.94) v1(74.28,23.89) v1(74.42,48.69) v1(75.42,48.69) v1(75.44,5.83) v1(75.78,60.94) v1(76.42,48.69) v1(77.78,60.94) v1(78.95,35.25) v1(79.25,5.83) v1(79.95,35.25) v1(80.95,35.25) v1(81.86,14.12) v1(81.95,35.25) v1(82.95,35.25) v1(83.74,80.46) v1(83.95,35.25) v1(84.95,35.25) v1(86.87,5.83) v1(87.38,79.37) v1(88.62,26.78) v1(88.62,25.78) v1(88.83,39.77) v1(89.83,39.77) v1(90.37,58.26) v1(90.47,14.35) v1(90.68,5.83) v1(90.83,39.77) v1(91.1,63.86) v1(91.83,39.77) v1(92.1,63.86) v1(92.1,62.86) v1(92.51,79.88) v1(92.83,39.77) v1(93.1,63.86) v1(93.1,62.86) v1(93.09,59.75) v1(93.83,39.77) v1(94.1,63.86) v1(94.1,62.86) v1(94.49,5.83) v1(95.1,63.86) v1(95.1,62.86) v1(95.68,26.84) v1(95.68,25.84) v1(95.68,24.84) v1(96.1,63.86) v1(96.1,62.86) v1(96.42,39.77) v1(96.77,81.68) v1(96.77,80.68) v1(96.91,66.47) v1(97.42,39.77) v1(97.74,29.26) v1(98.3,5.83) v1(98.42,39.77) v1(98.6,35.25) v1(98.74,29.26) v1(99.42,39.77) v1(99.67,88.73) v1(99.67,87.73) v1(100.08,80.37) v1(100.42,39.77) v1(101.05,26.51) v1(101.12,21.03) v1(101.42,39.77) v1(102.06,80.37) v1(102.12,21.03) v1(102.05,12.29) v1(102.11,5.83) v1(102.42,39.77) v1(102.87,35.28) v1(103.06,80.37) v1(103.07,79.07) v1(103.05,12.29) v1(103.42,39.77) v1(103.87,35.28) v1(104.01,92.64) v1(104.05,12.29) v1(104.42,39.77) v1(104.87,35.28) v1(105.05,12.29) v1(105.42,39.77) v1(105.75,79.04) v1(105.84,73.49) v1(105.87,35.28) v1(105.92,5.83) v1(106.25,60.7) v1(106.42,39.77) v1(106.76,82.72) v1(106.75,79.04) v1(106.83,73.49) v1(106.9,95.94) v1(106.9,95.14) v1(106.9,94.34) v1(106.93,89.71) v1(107.62,35.25) v1(107.7,95.94) v1(107.7,95.14) v1(107.7,94.34) v1(107.76,82.72) v1(107.75,79.04) v1(107.83,73.49) v1(107.8,29.33) v1(108.5,95.94) v1(108.5,95.14) v1(108.5,94.34) v1(108.62,35.25) v1(108.75,79.04) v1(108.97,12.9) v1(109.17,60.73) v1(109.62,73.37) v1(109.73,5.83) v1(109.86,29.33) v1(110.72,82.72) v1(110.85,29.33) v1(111,12.9) v1(111.72,82.72) v1(112.52,60.75) v1(112.72,82.72) v1(113.54,61.77) v1(113.52,29.33) v1(113.54,5.83) v1(113.72,82.72) v1(113.97,59.51) v1(114.36,45.36) v1(114.36,44.36) v1(114.6,56.77) v1(114.65,55.44) v1(114.93,63.84) v1(115.93,63.84) v1(116.71,42.19) v1(116.87,15.69) v1(116.87,14.69) v1(116.98,80.36) v1(117.35,5.83) v1(117.69,36.04) v1(117.9,99.17) v1(118.29,95.88) v1(118.49,14.02) v1(118.5,12.39) v1(118.62,42.19) v1(119.29,95.88) v1(119.44,29.33) v1(119.5,12.39) v1(119.81,44.56) v1(119.81,43.56) v1(119.94,39.8) v1(120.29,95.88) v1(120.5,12.39) v1(120.94,39.8) v1(121.16,5.83) v1(121.41,20.61) v1(122.18,26.29) v1(122.41,20.61) v1(122.41,19.61) v1(122.56,83.26) v1(122.56,81.11) v1(122.63,30.98) v1(122.81,60.68) v1(123.3,63.68) v1(123.39,12.39) v1(123.63,30.98) v1(124.05,55.42) v1(124.18,26.29) v1(124.3,63.68) v1(124.28,12.39) v1(124.48,72.57) v1(124.63,30.98) v1(124.72,29.16) v1(124.91,94.61) v1(124.97,5.83) v1(125.07,83.28) v1(125.1,78.58) v1(125.18,26.29) v1(125.3,63.68) v1(125.3,37.77) v1(125.3,36.77) v1(125.63,30.98) v1(125.73,52.25) v1(125.73,51.25) v1(125.72,29.16) v1(126.3,63.68) v1(126.3,62.41) v1(126.63,30.98) v1(126.73,52.25) v1(126.72,29.16) v1(127.18,12.39) v1(127.3,65.68) v1(127.63,30.98) v1(127.72,29.16) v1(127.81,83.26) v1(127.81,81.11) v1(128.3,65.68) v1(128.25,39.64) v1(128.63,30.98) v1(128.72,29.16) v1(128.78,5.83) v1(129.33,99.17) v1(129.3,65.68) v1(129.72,29.16) v1(130.07,73.91) v1(130.18,10.5) v1(131.04,59.58) v1(131.24,89.94) v1(131.18,10.5) v1(131.34,83.36) v1(131.83,60.55) v1(132.03,46.38) v1(132.08,78.66) v1(132.22,40.64) v1(132.33,80.91) v1(133.4,19.07) v1(134.11,60.8) v1(134.14,20.95) v1(134.4,19.07) v1(134.75,52.17) v1(135.11,60.8) v1(135.45,71.72) v1(135.4,19.07) v1(135.75,52.17) v1(135.79,36.75) v1(136.02,40.36) v1(135.98,28.52) v1(135.98,27.52) v1(135.98,26.52) v1(135.98,25.52) v1(135.98,24.52) v1(136.4,19.07) v1(136.95,99.17) v1(136.93,88.08) v1(137.08,7.27) v1(137.76,16.3) v1(137.76,15.3) v1(137.94,86.15) v1(137.9,49.2) v1(138.08,8.27) v1(138.08,7.27) v1(138.08,6.27) v1(138.48,33.85) v1(138.76,16.3) v1(138.76,15.3) v1(140.21,5.83) v1(140.76,99.17) v1(141.43,19.3) v1(141.83,50.67) v1(142.27,17.14) v1(142.83,50.67) v1(143.15,93.3) v1(143.15,90.75) v1(143.08,67.88) v1(143.08,63.61) v1(143.71,36.24) v1(143.76,32.51) v1(143.81,18.46) v1(143.97,86.78) v1(144.02,5.83) v1(144.08,63.61) v1(144.37,82.7) v1(144.37,72.39) v1(144.57,99.17) v1(144.65,93.3) v1(144.65,90.75) v1(144.71,36.24) v1(144.68,21.97) v1(144.76,32.51) v1(145.59,25.71) v1(145.75,49.22) v1(145.71,37.24) v1(146.15,93.3) v1(146.15,90.75) v1(146.33,19.99) v1(146.35,56.74) v1(146.41,23.11) v1(146.63,71.34) v1(146.59,25.71) v1(146.69,67.01) v1(146.69,62.82) v1(146.75,49.22) v1(146.71,44.91) v1(146.86,86.78) v1(147.42,18.56) v1(147.59,25.71) v1(147.65,93.3) v1(147.65,90.75) v1(147.75,49.22) v1(147.71,37.24) v1(147.83,5.83) v1(148.38,99.17) v1(148.59,25.71) v1(148.71,37.24) v1(148.72,35.04) v1(148.72,34.04) v1(149.15,93.3) v1(149.15,90.75) v1(149.41,14.3) v1(149.71,37.24) v1(149.72,35.04) v1(149.72,34.04) v1(149.78,86.78) v1(149.76,32.51) v1(150.27,76.43) v1(150.28,70.31) v1(150.28,68.01) v1(150.28,67.01) v1(150.28,59.78) v1(150.35,45.22) v1(150.35,42.22) v1(150.35,41.22) v1(150.41,15.3) v1(150.41,14.3) v1(150.65,93.3) v1(151.41,15.3) v1(151.41,14.3) v1(151.64,5.83) v1(152.07,89.85) v1(152.19,99.17) v1(152.7,67.53) v1(152.7,65.53) v1(152.7,64.53) v1(152.7,59.78) v1(152.7,57.5) v1(152.81,77.93) v1(152.81,74.93) v1(152.81,73.43) v1(152.85,44.22) v1(152.85,43.22) v1(152.85,42.22) v1(154.84,77.9) v1(154.84,76.5) v1(154.84,74.98) v1(154.84,73.45) v1(154.96,70.43) v1(155.14,90.79) v1(155.14,89.79) v1(155.14,88.79) v1(155.52,56.74) v1(155.52,53.85) v1(156.14,88.79) v1(157.17,93.05) v1(157.17,89.24) v1(157.17,85.43) v1(157.17,81.62) v1(157.17,77.81) v1(157.17,74) v1(157.17,70.19) v1(157.17,66.38) v1(157.17,62.57) v1(157.17,58.76) v1(157.17,54.95) v1(157.17,51.14) v1(157.17,43.52) v1(157.17,39.71) v1(157.17,35.9) v1(157.17,32.09) v1(157.17,28.28) v1(157.17,24.47) v1(157.17,20.66) v1(157.17,16.85) v1(157.17,13.04)
